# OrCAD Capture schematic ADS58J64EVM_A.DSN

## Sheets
1 PAGE06 - OUTPUT - XILINX CONN: size B; title: OUTPUT - FMC ONNECTOR; rev: A; note: ADS58J64EVM
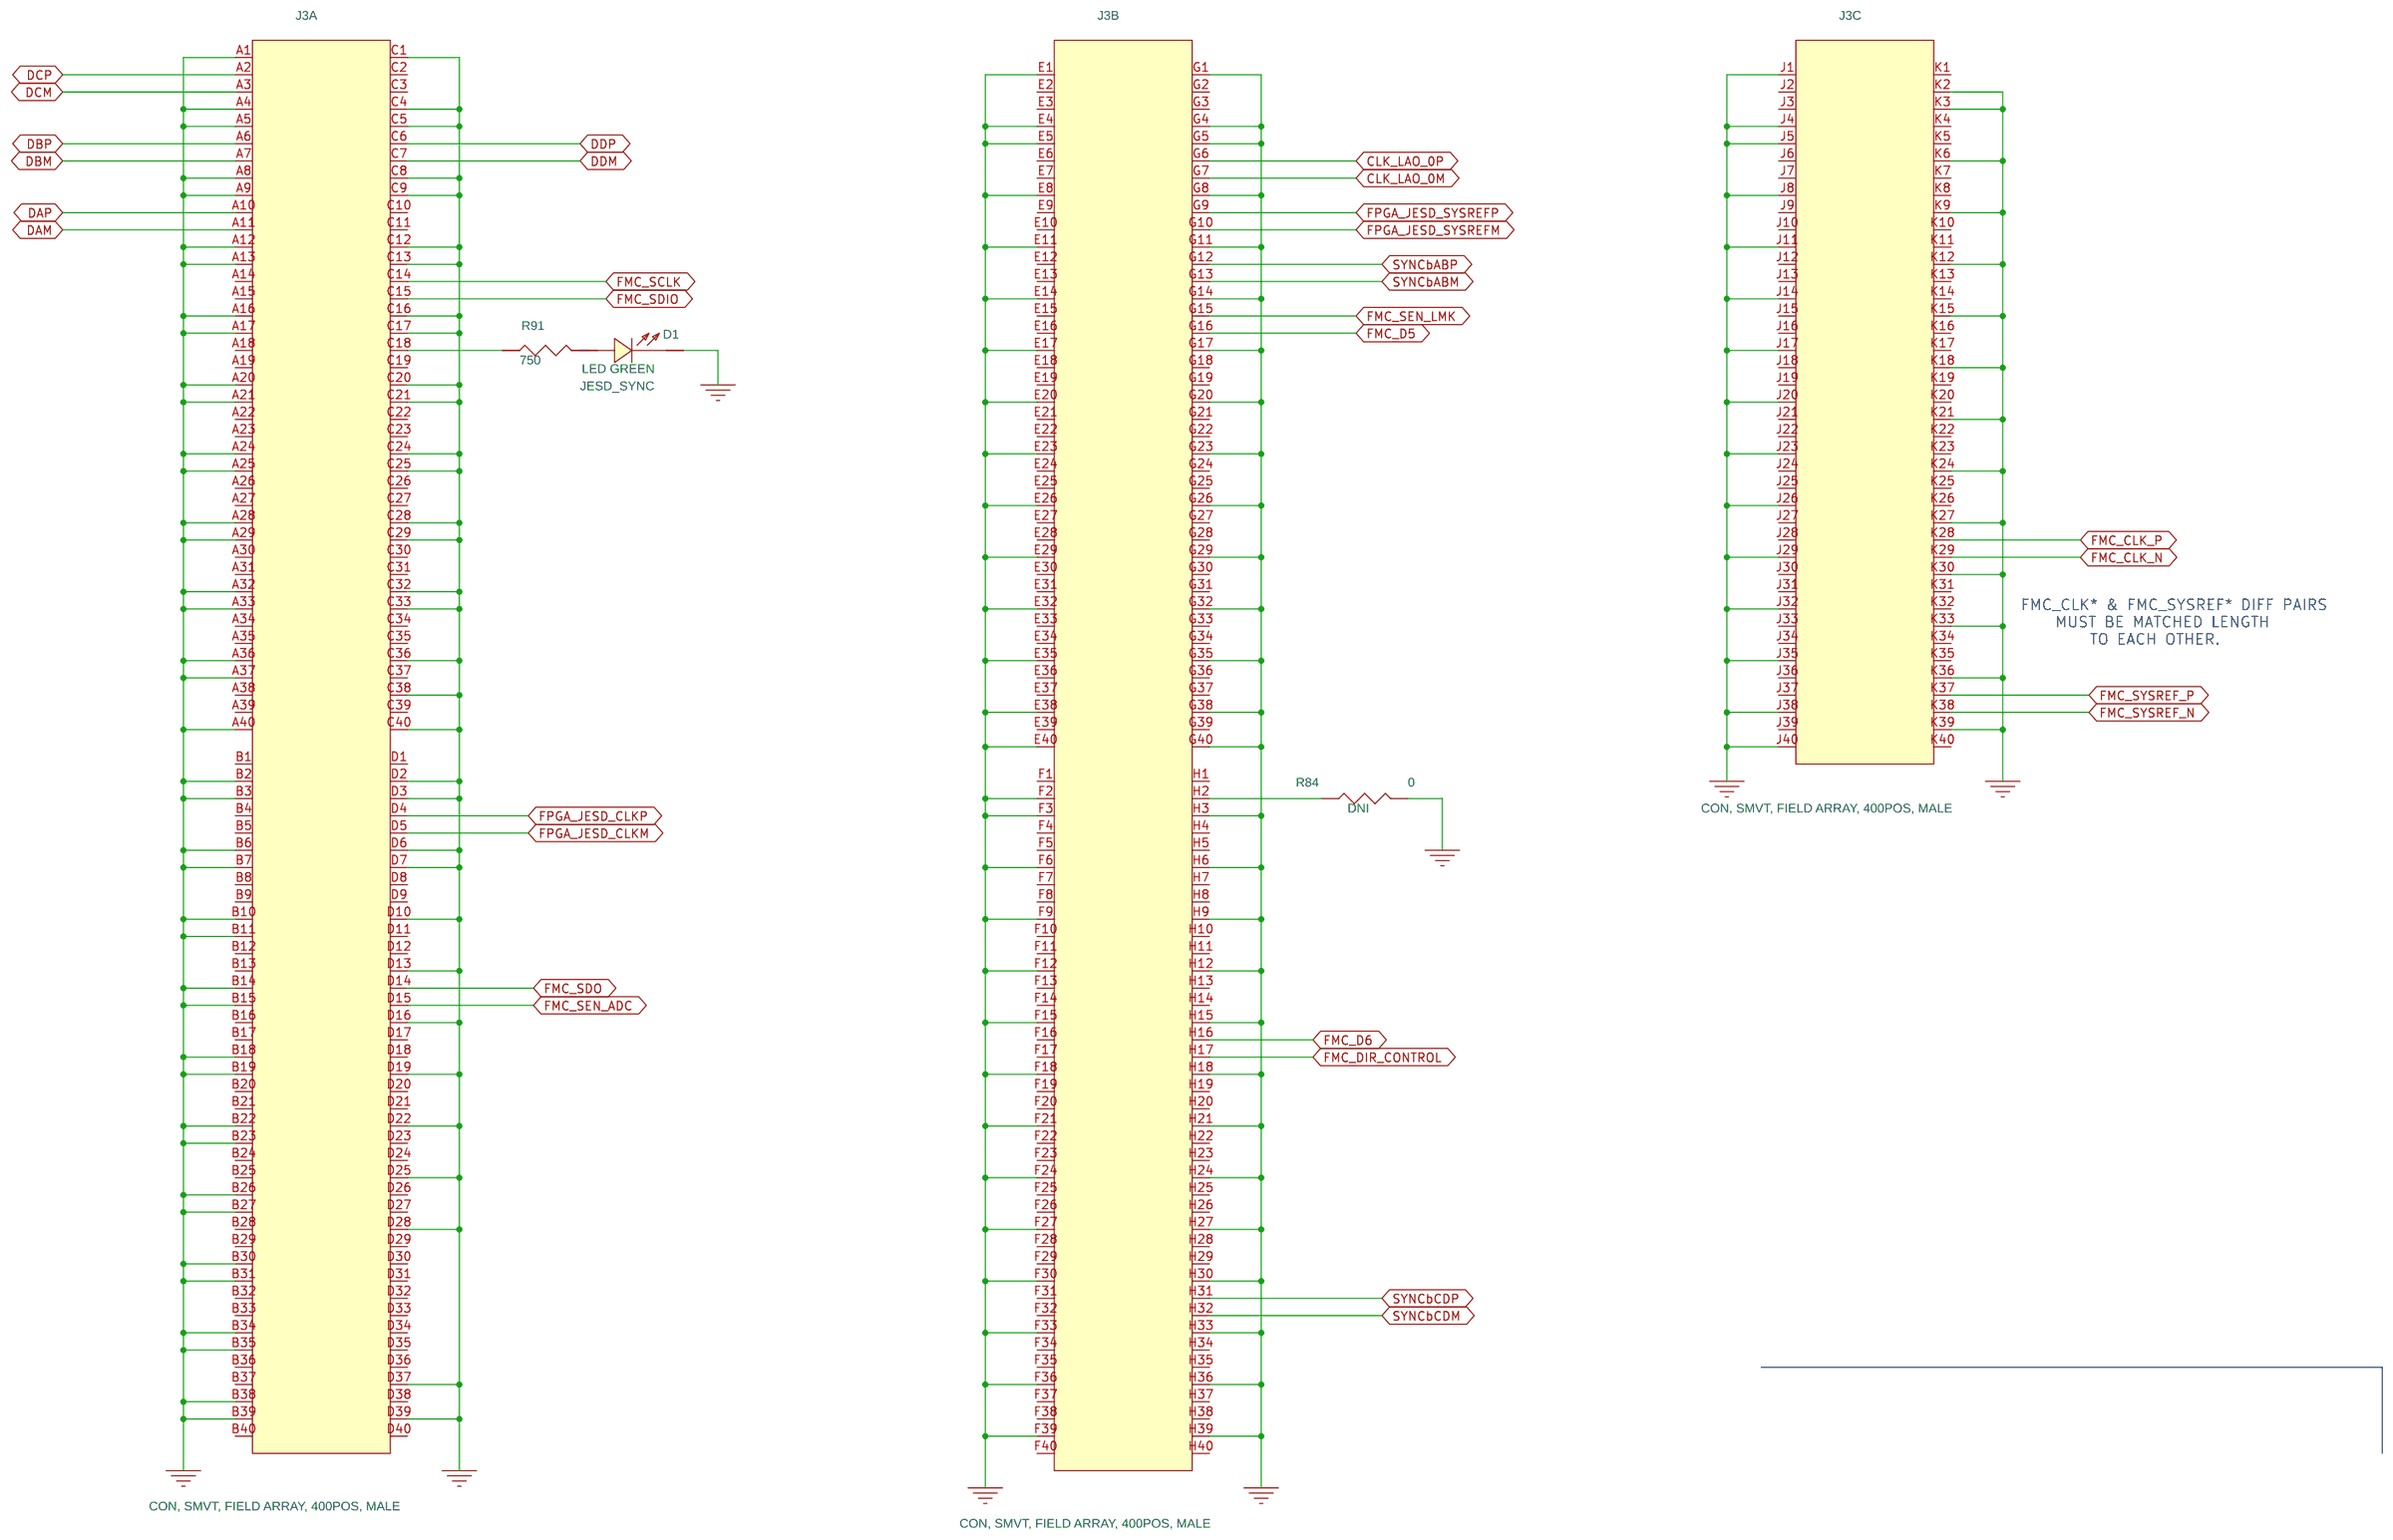
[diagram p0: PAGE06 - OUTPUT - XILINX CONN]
2 PAGE08-  CPLD: size B; title: CPLD
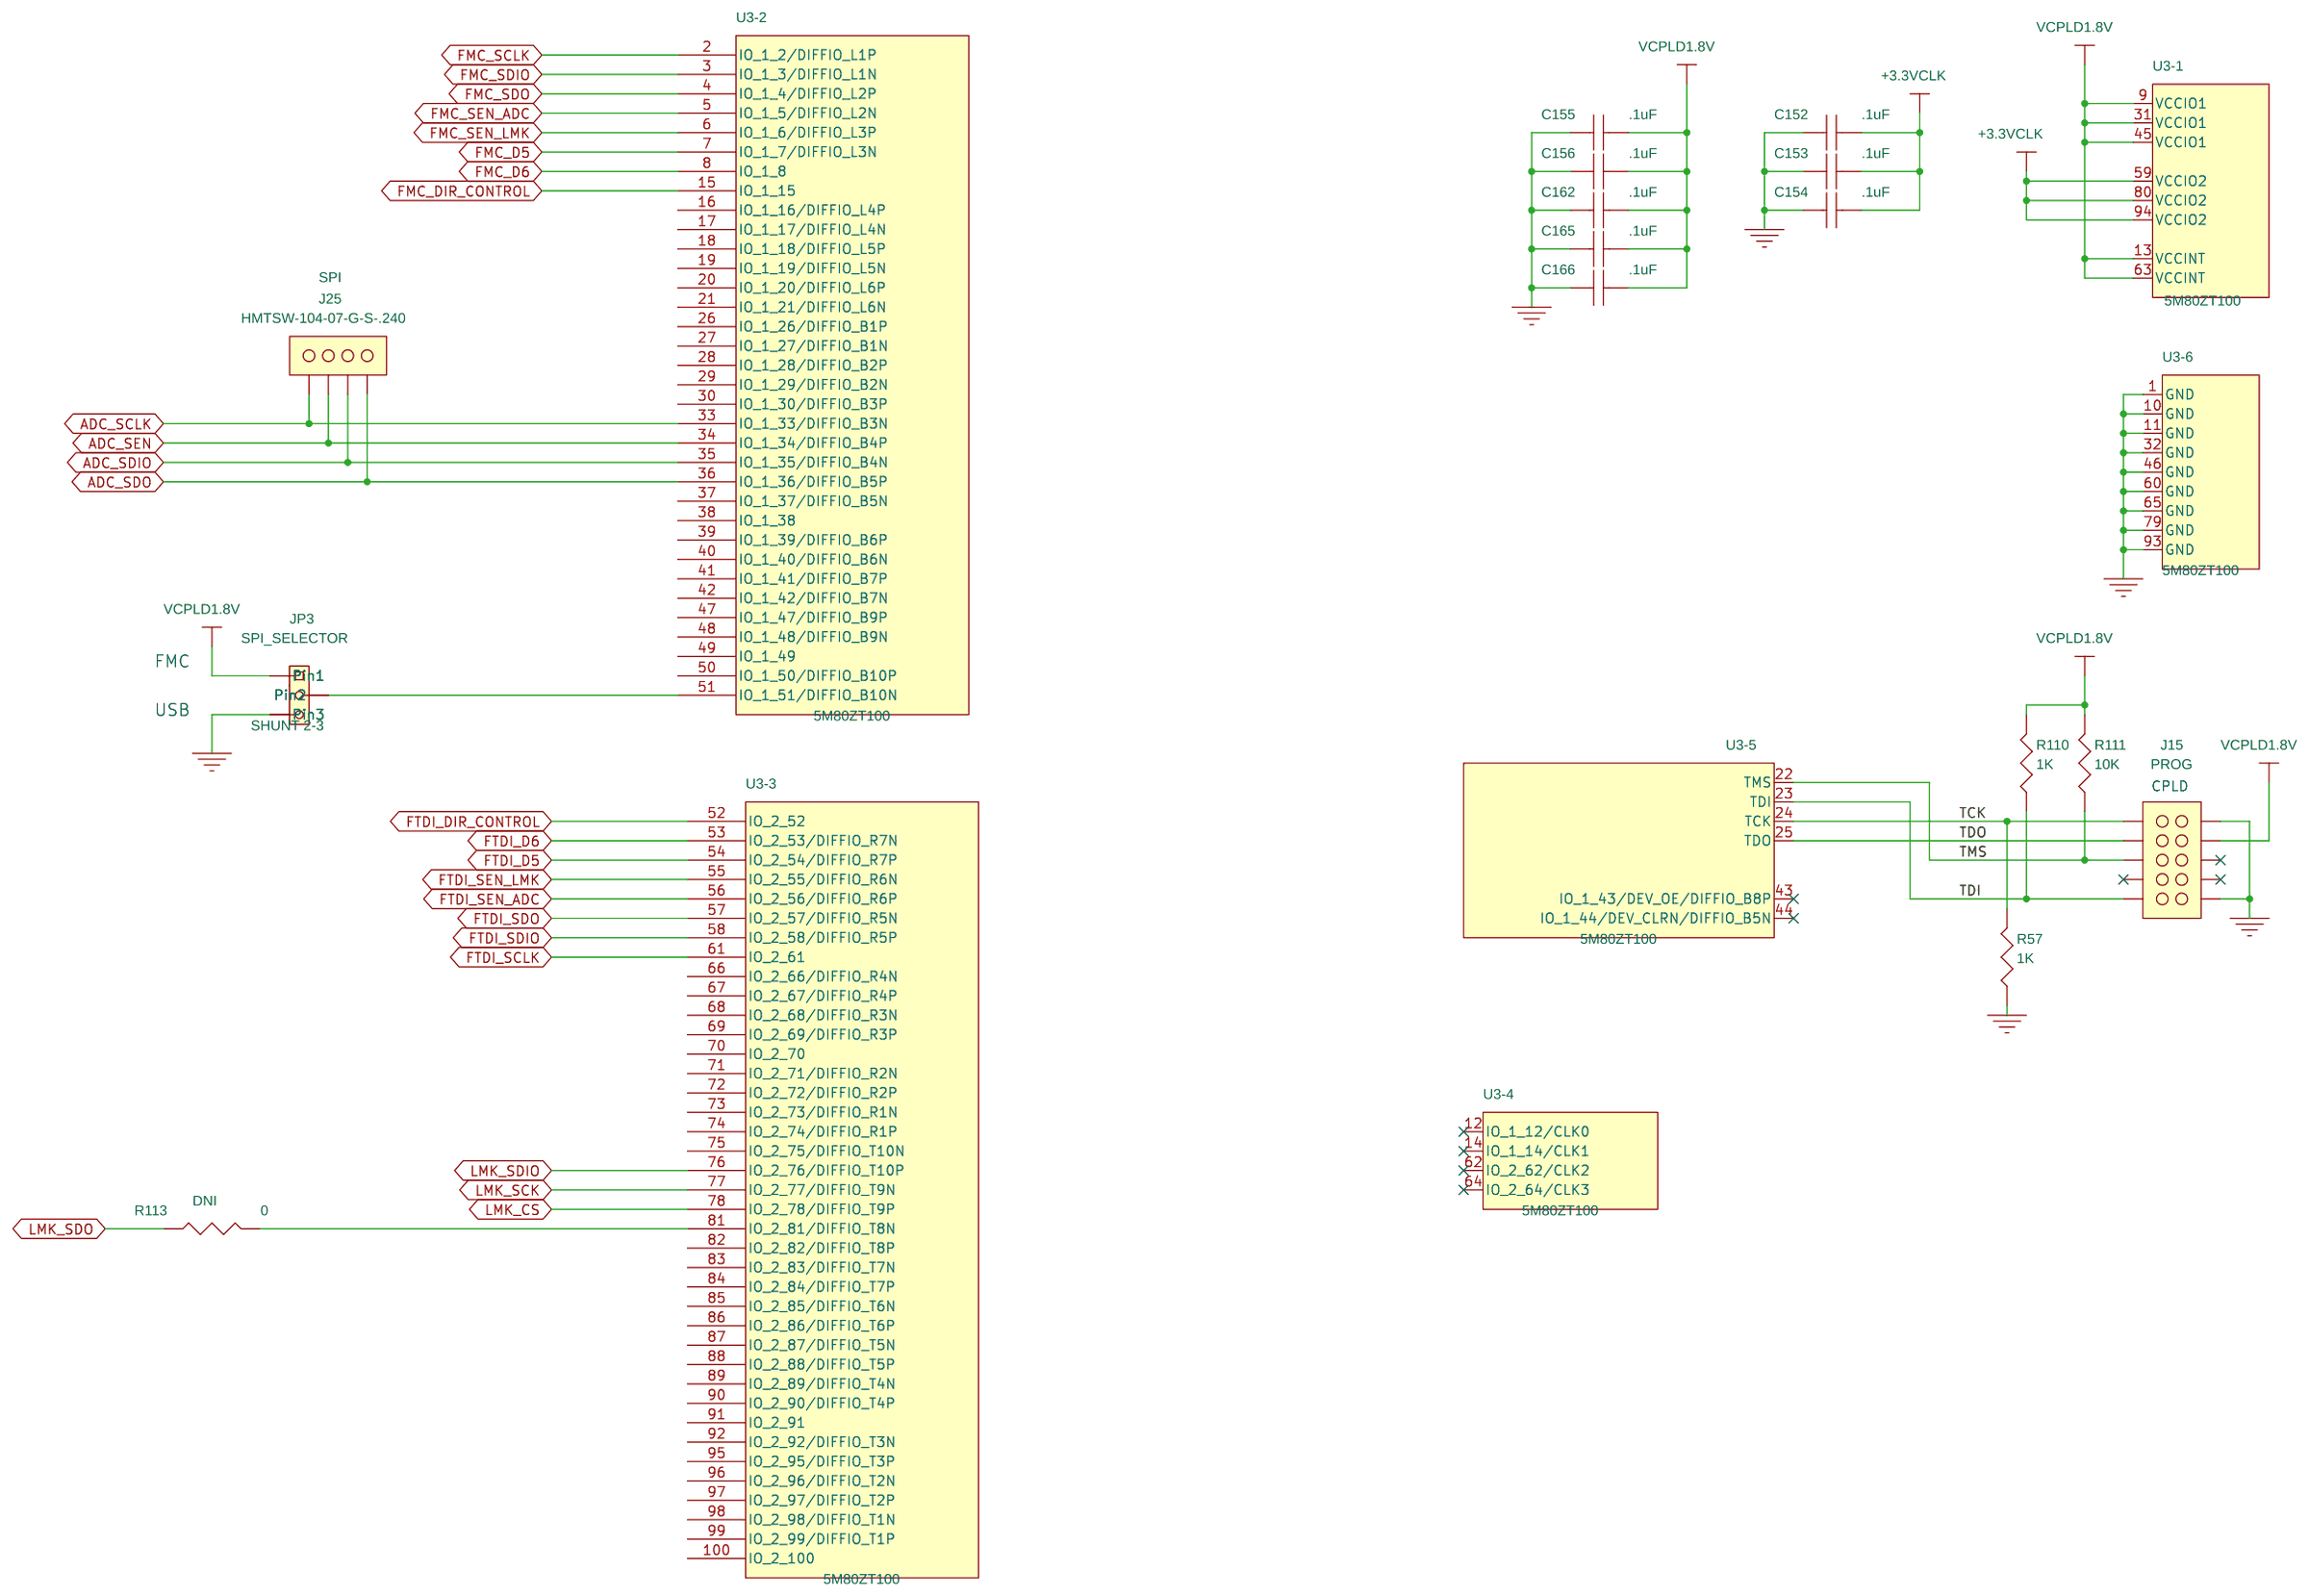
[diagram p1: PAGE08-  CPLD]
3 PAGE04 - LMK: size B; title: CLOCK
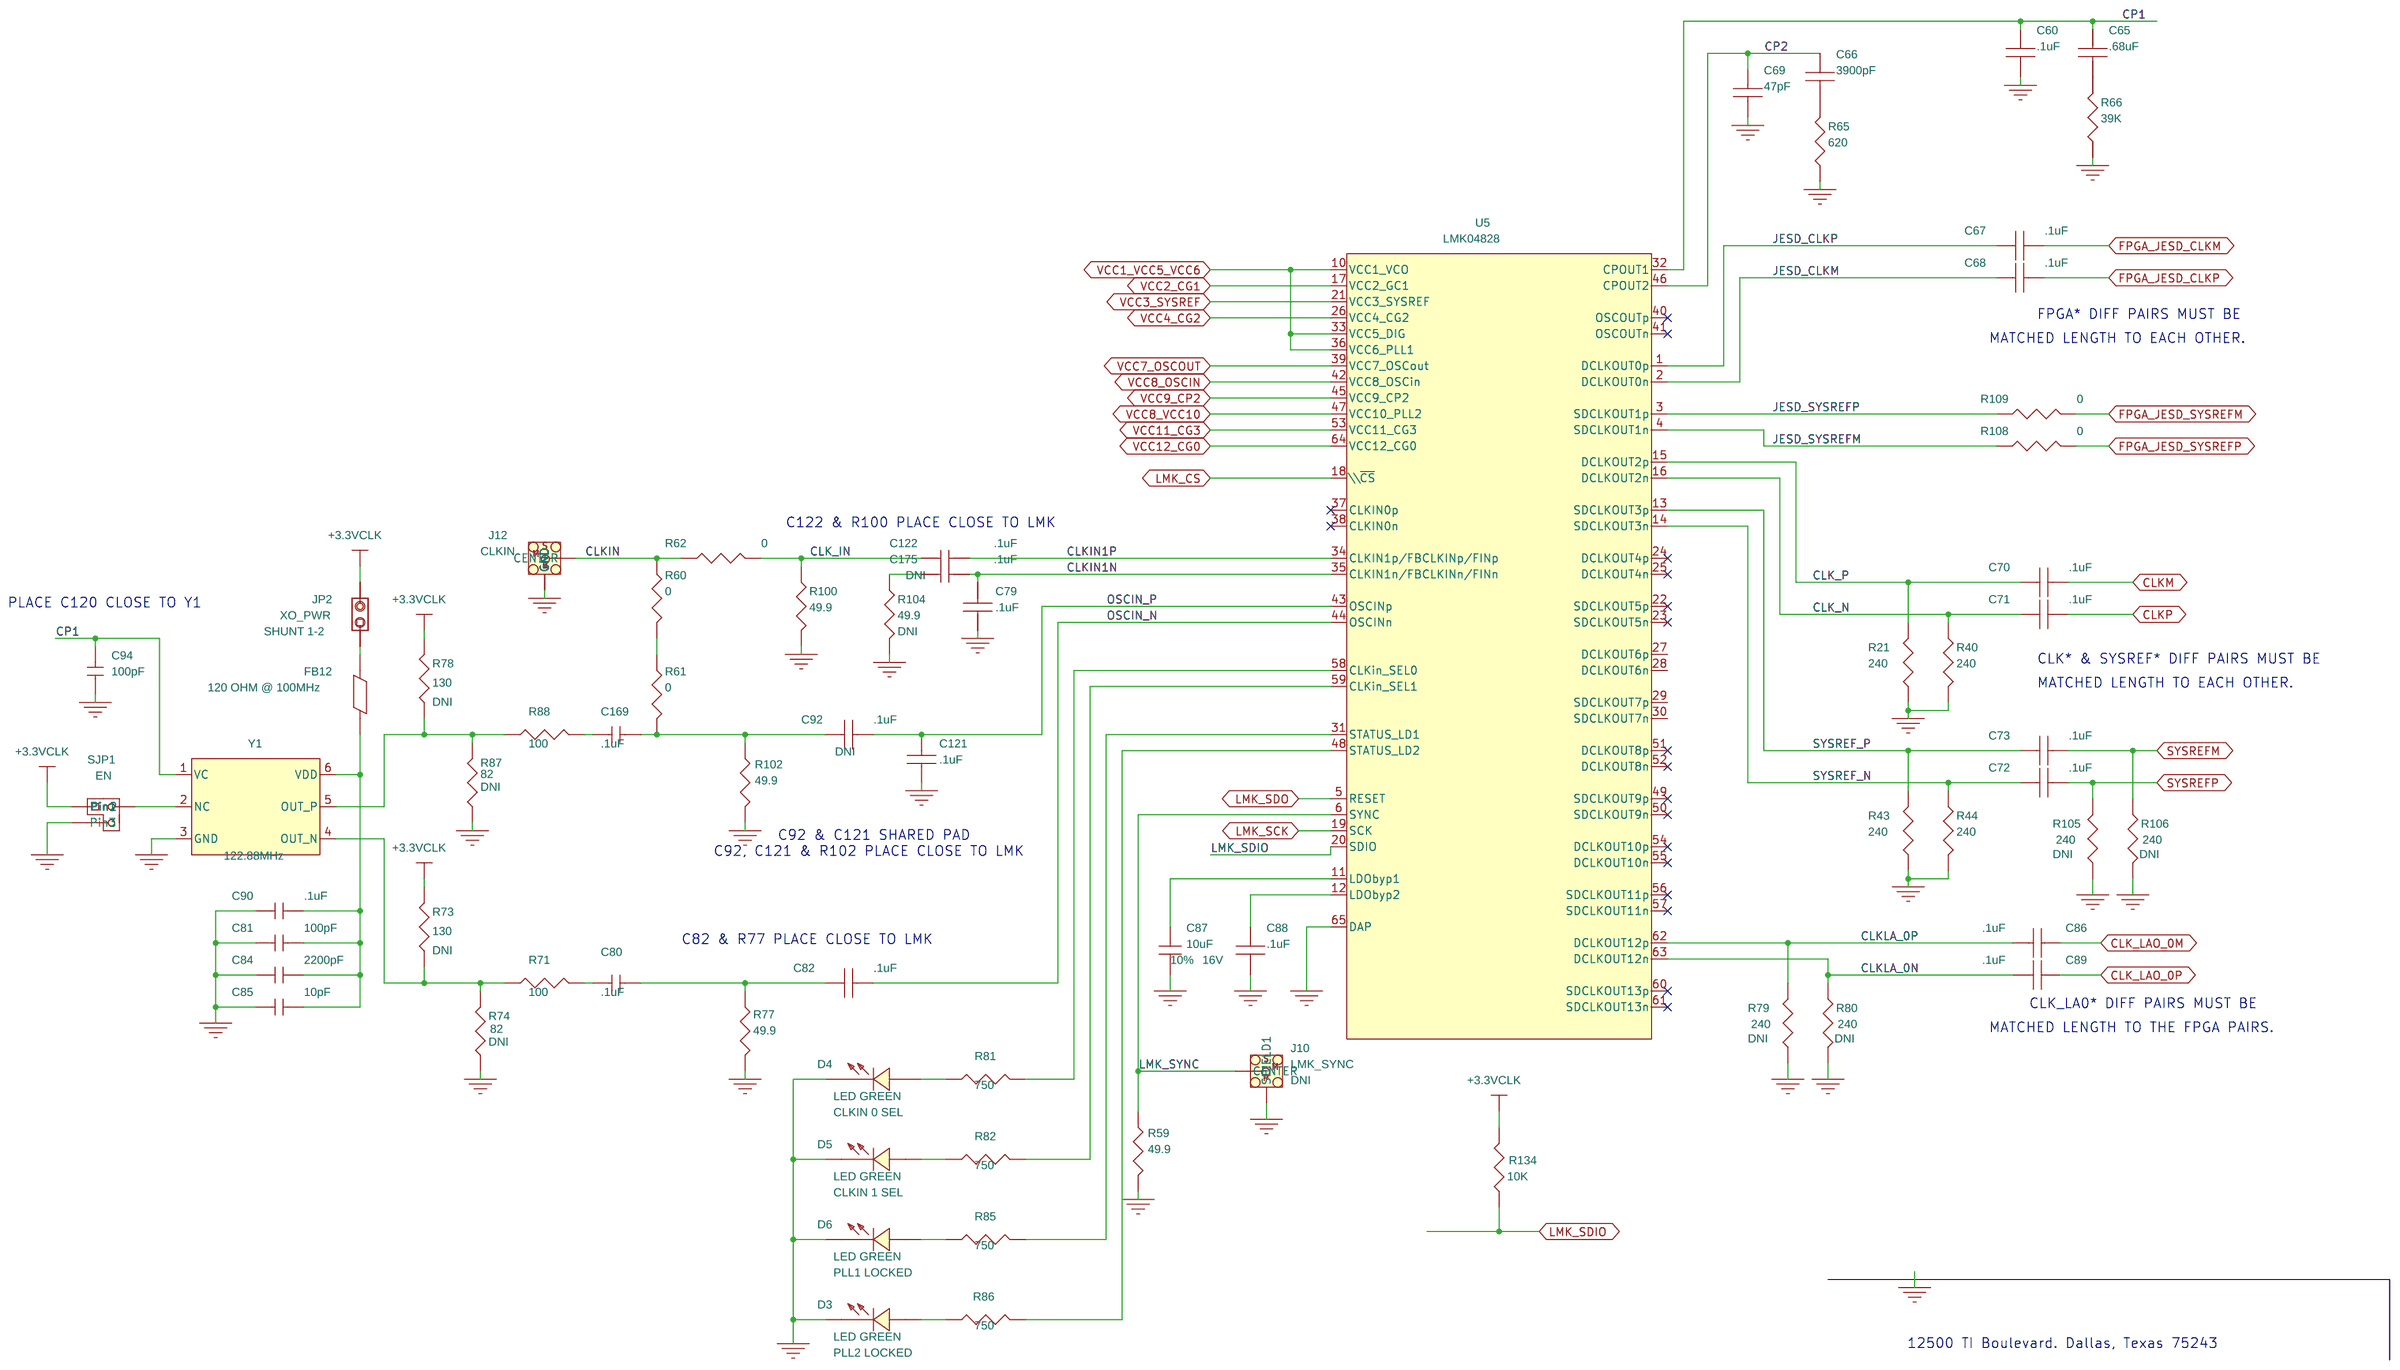
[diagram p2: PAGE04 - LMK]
4 PAGE01 - BLOCK DIAGRAM: title: BLOCK DIAGRAM
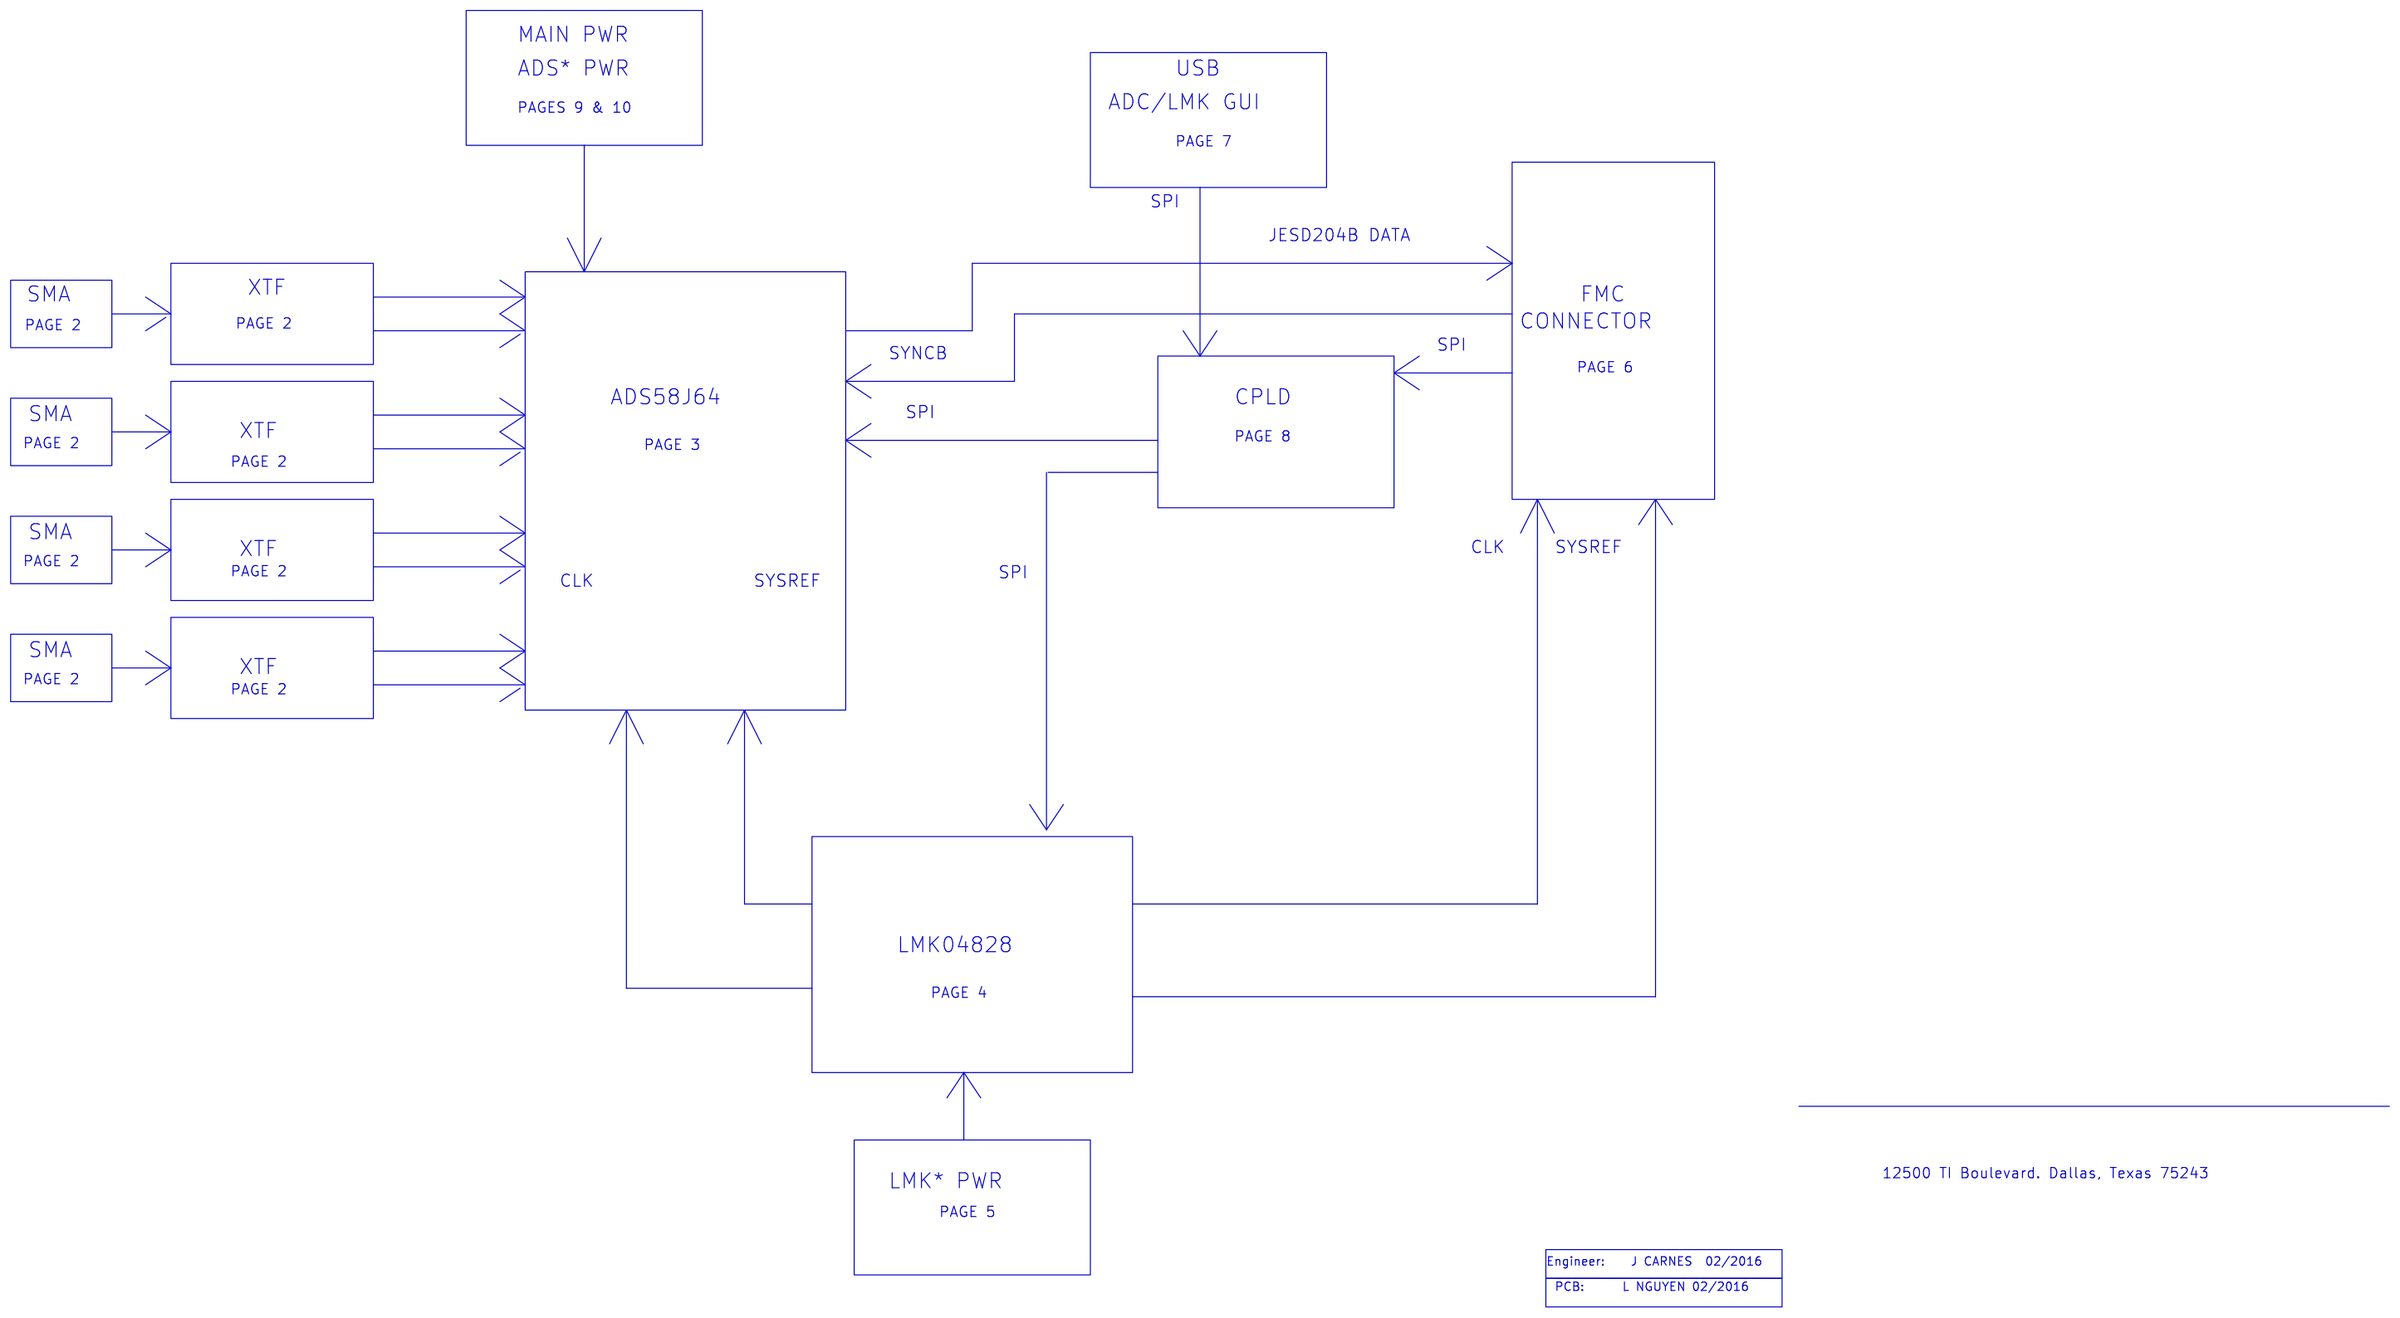
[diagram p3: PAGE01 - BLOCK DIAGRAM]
5 PAGE02 - ANALOG IN: size B; title: ANALOG IN
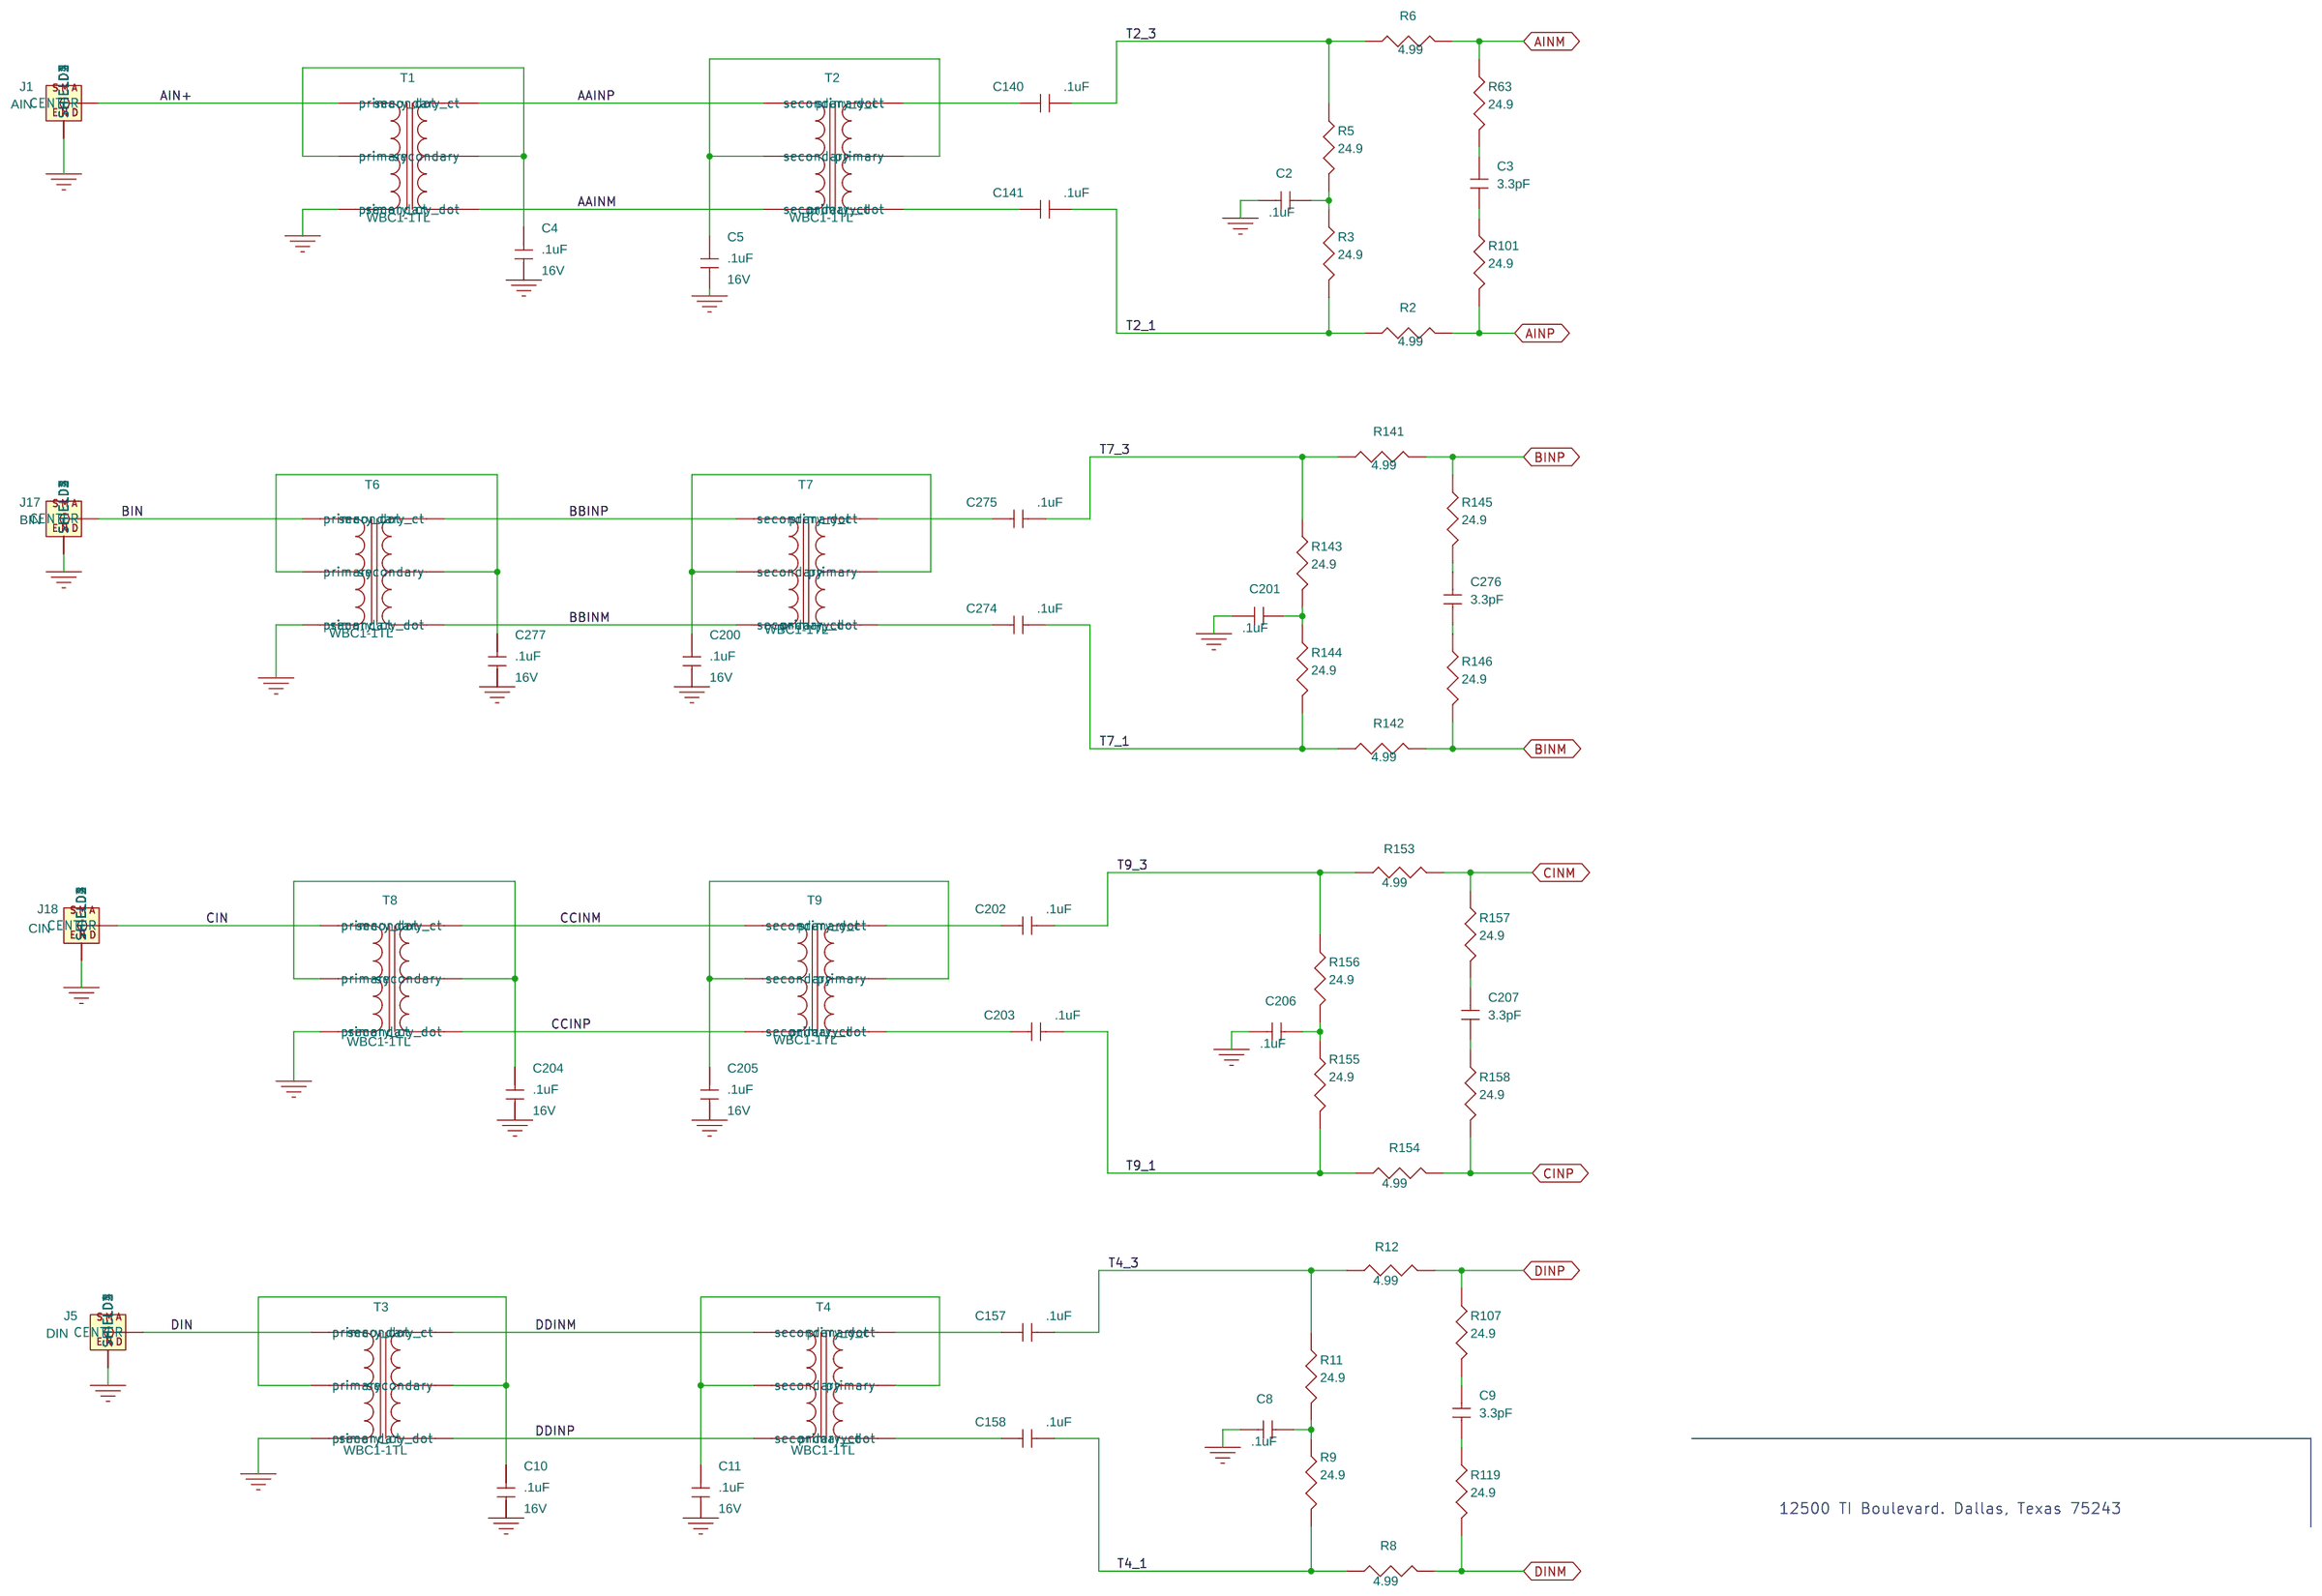
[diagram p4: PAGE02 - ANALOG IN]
6 PAGE03 - ADS58J66_DODSIS: size B; title: ADC
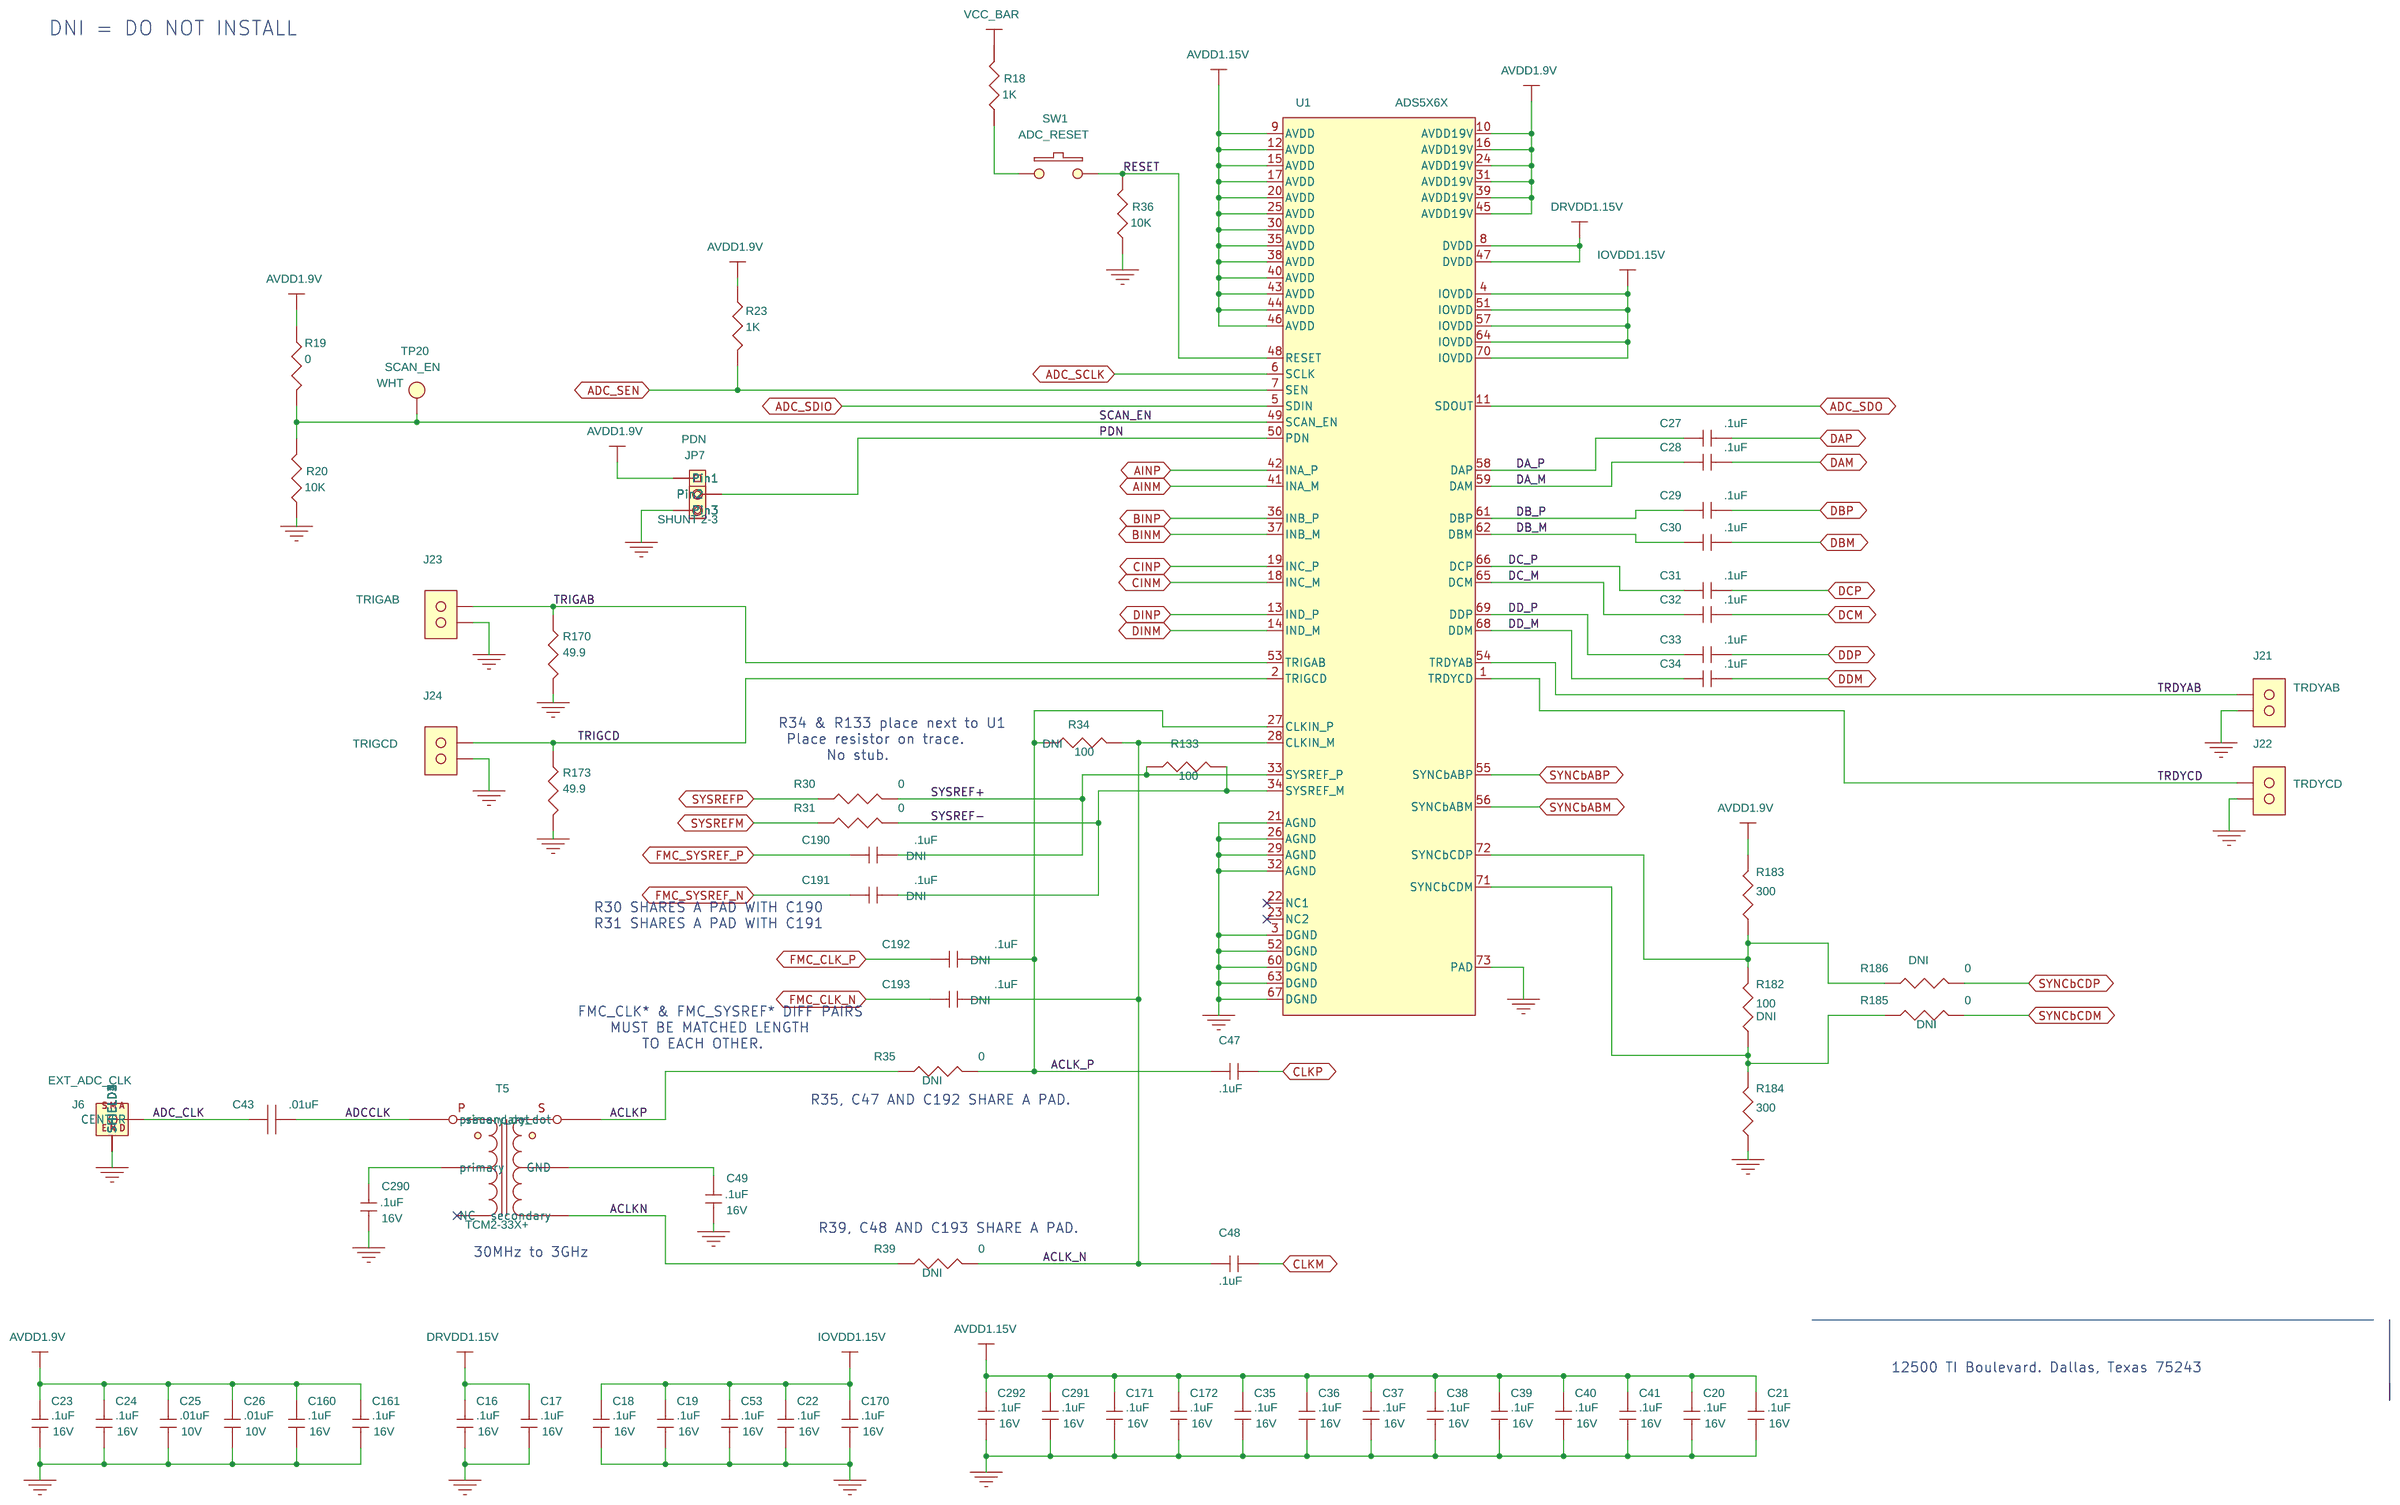
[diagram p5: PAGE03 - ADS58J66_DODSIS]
7 PAGE05 - LMK POWER: size B; title: LMK POWER
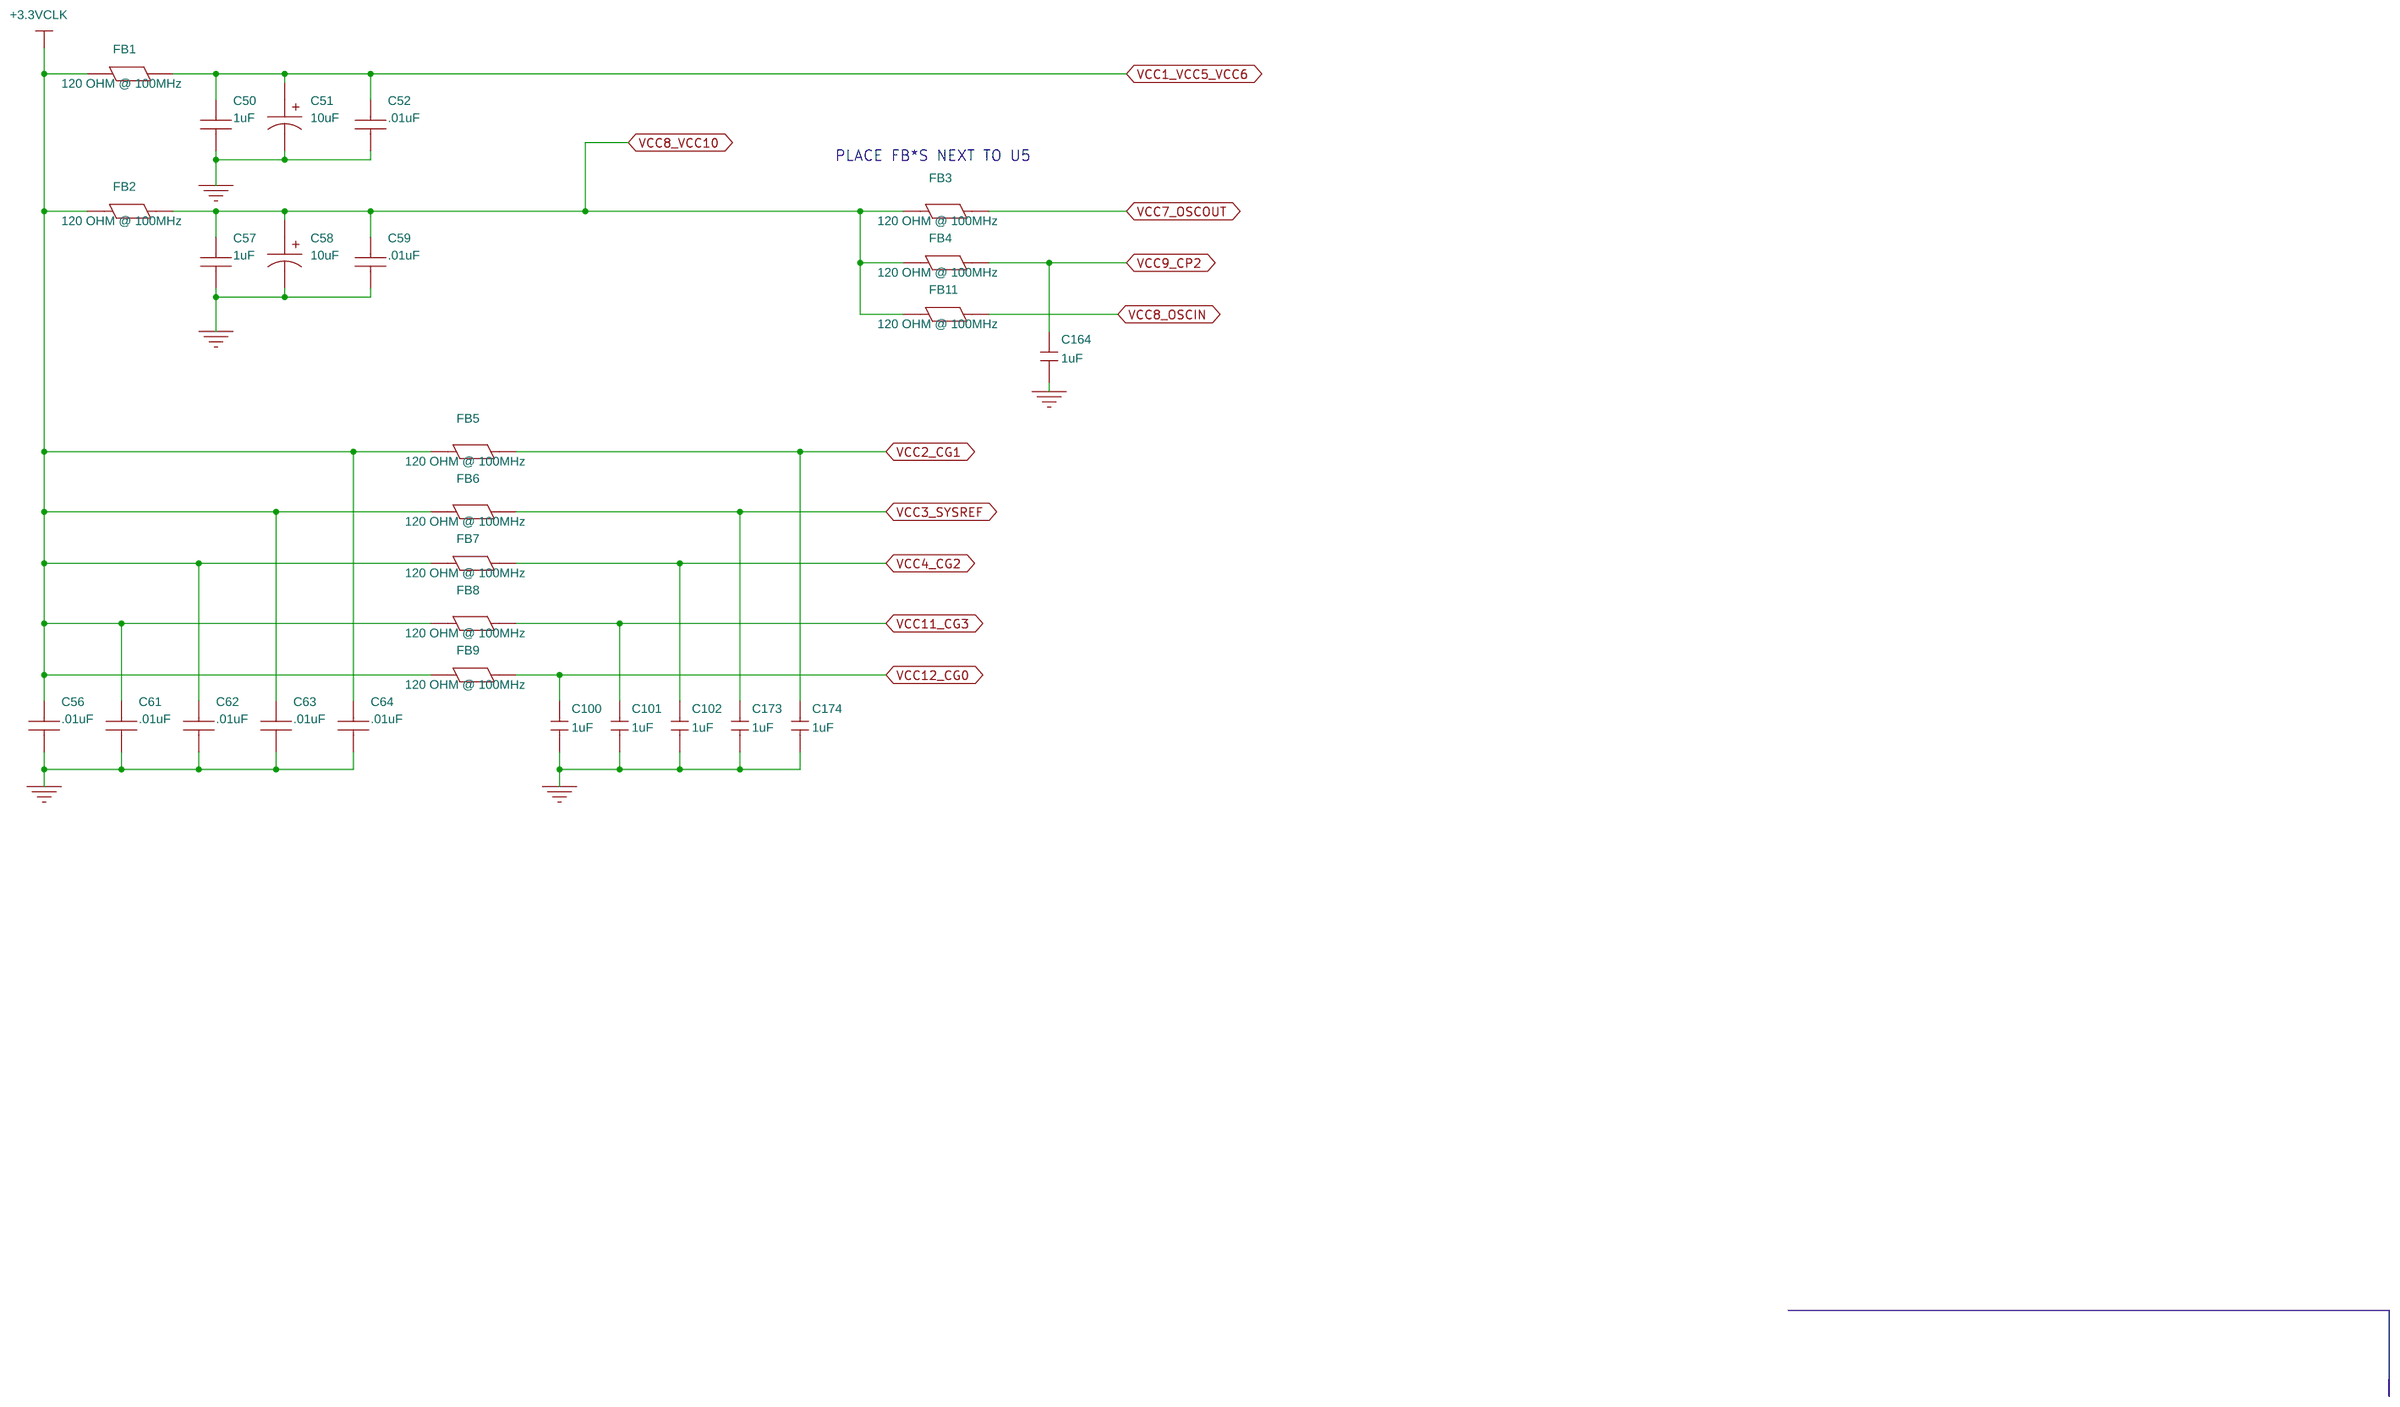
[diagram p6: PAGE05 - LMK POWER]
8 PAGE07 - USB INTERFACE: size B; title: USB
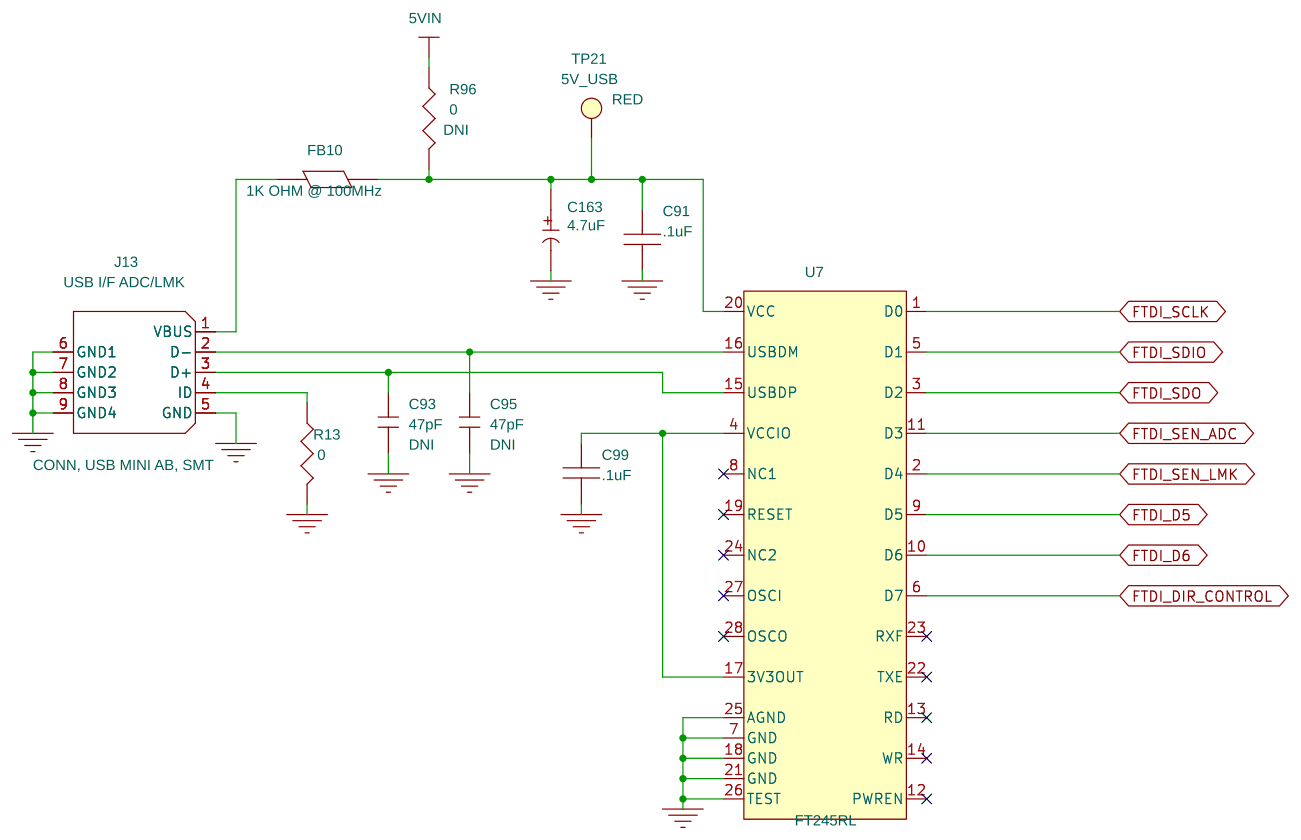
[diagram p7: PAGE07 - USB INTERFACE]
9 PAGE09 - MAIN POWER SUPPLIES: size B; title: MAIN POWER
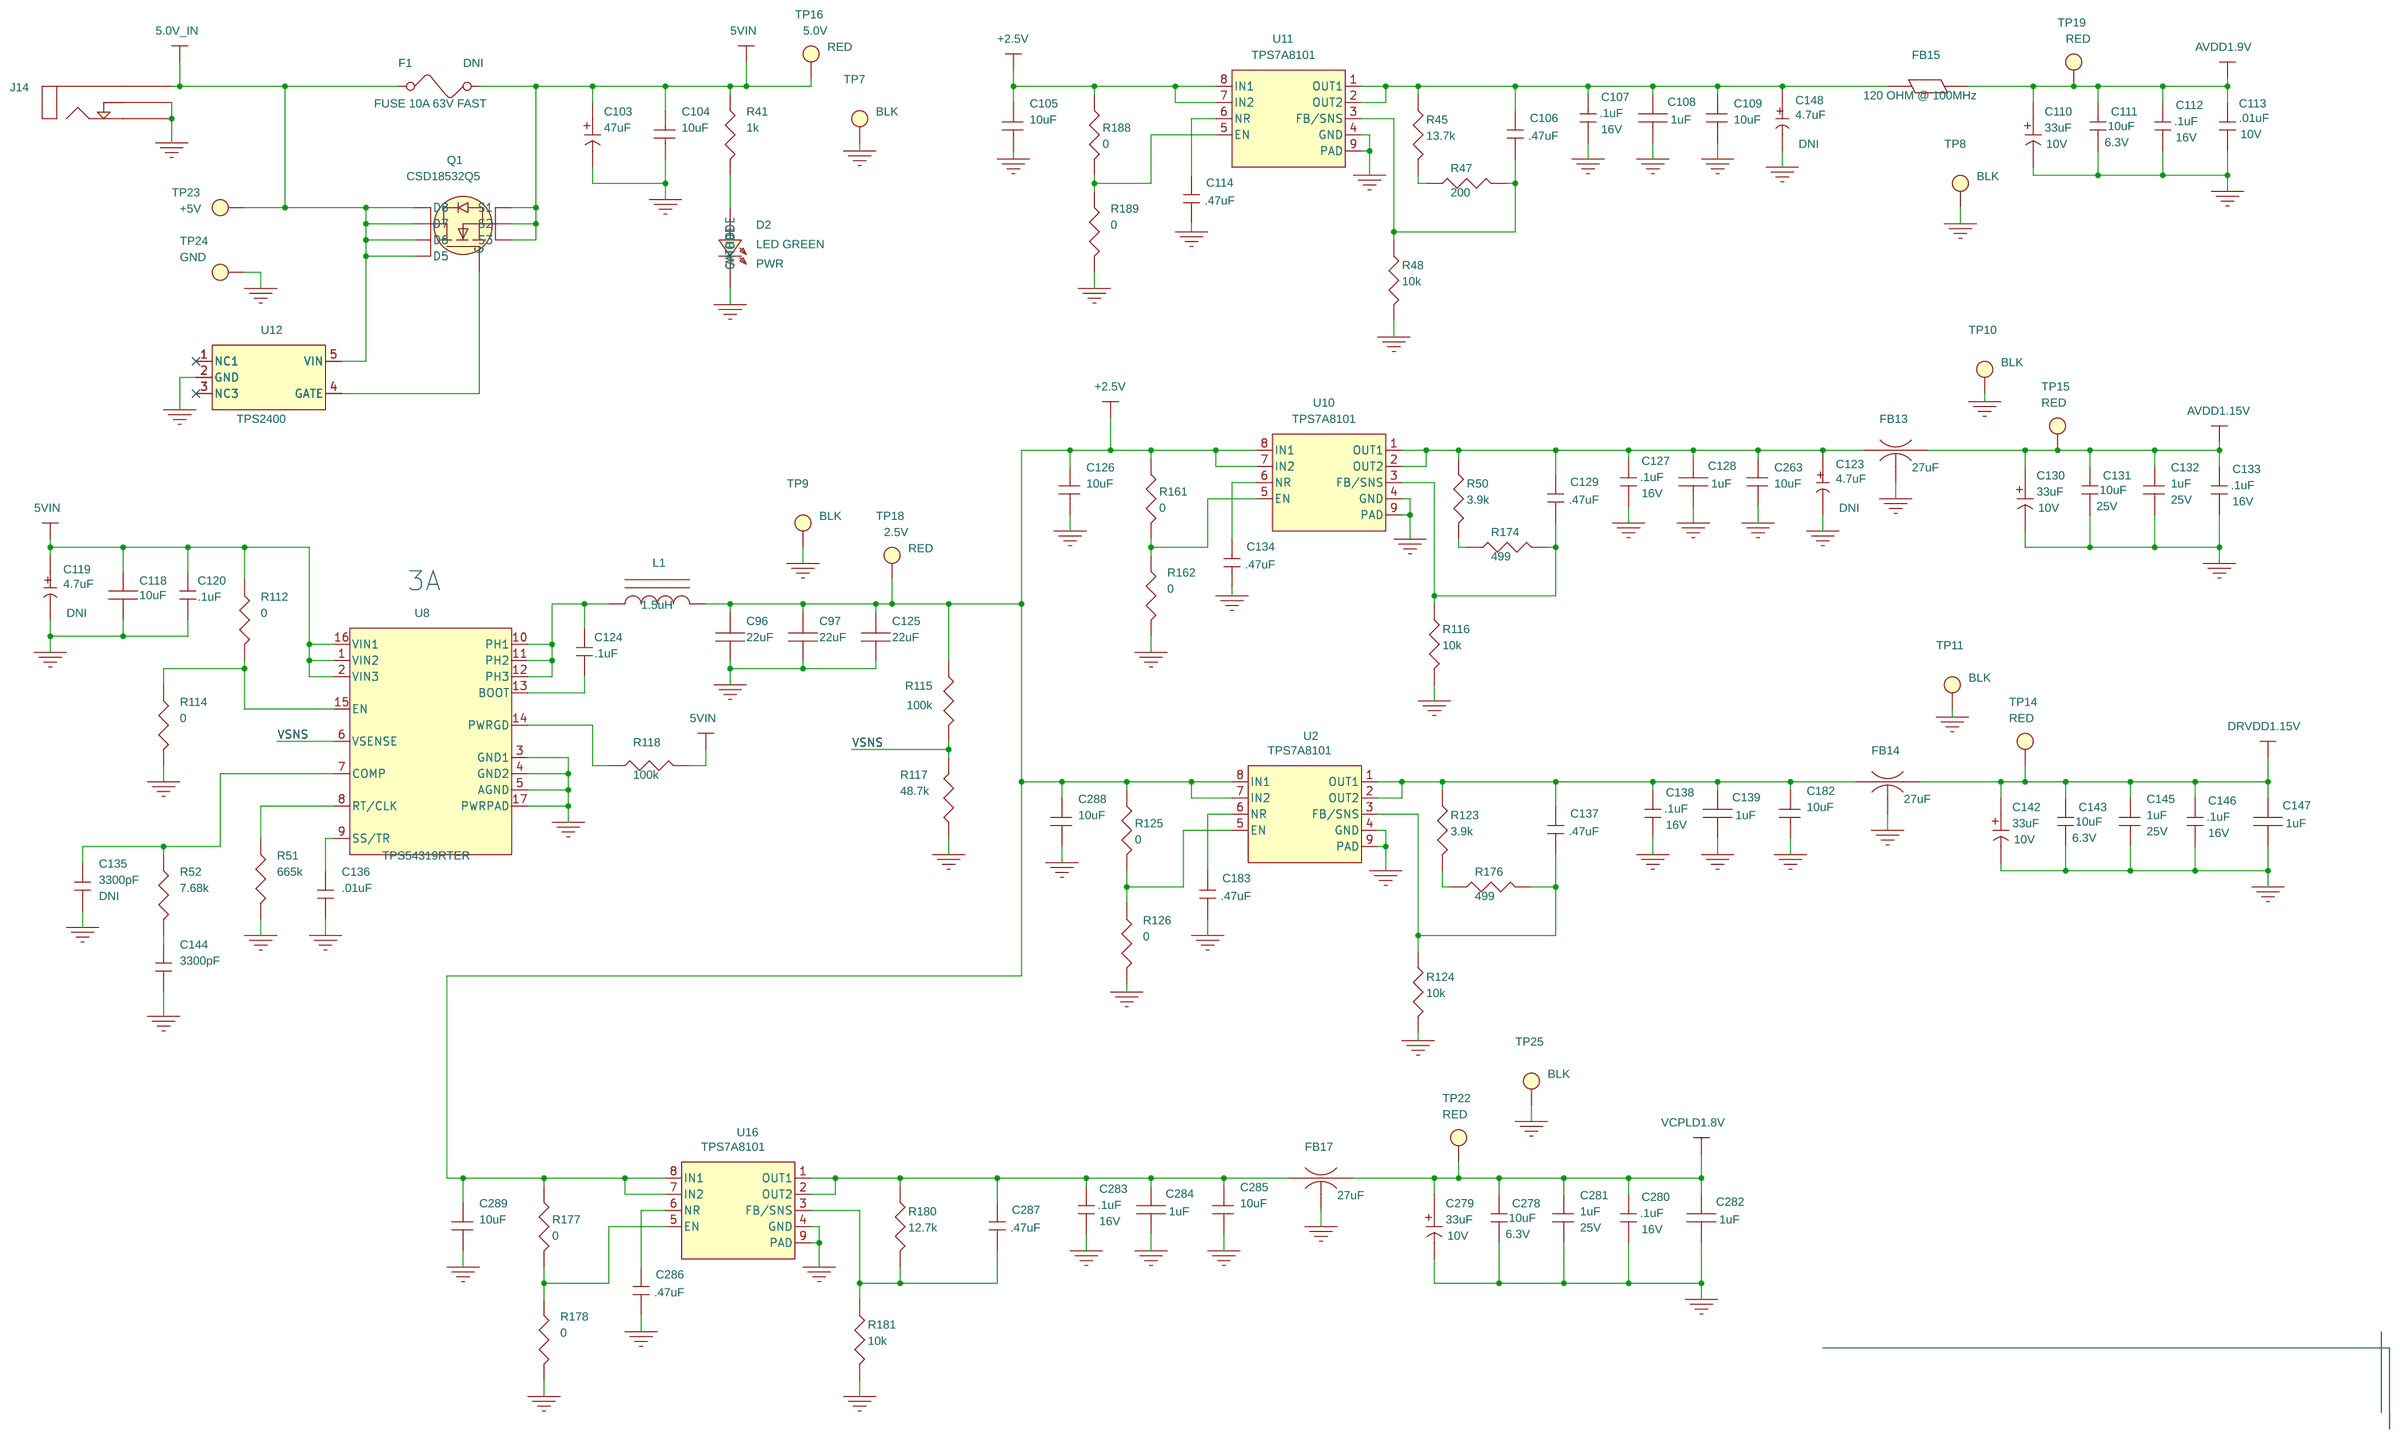
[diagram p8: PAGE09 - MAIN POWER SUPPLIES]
10 PAGE10 - PWR 3.3V: size B; title: POWER 3.3V
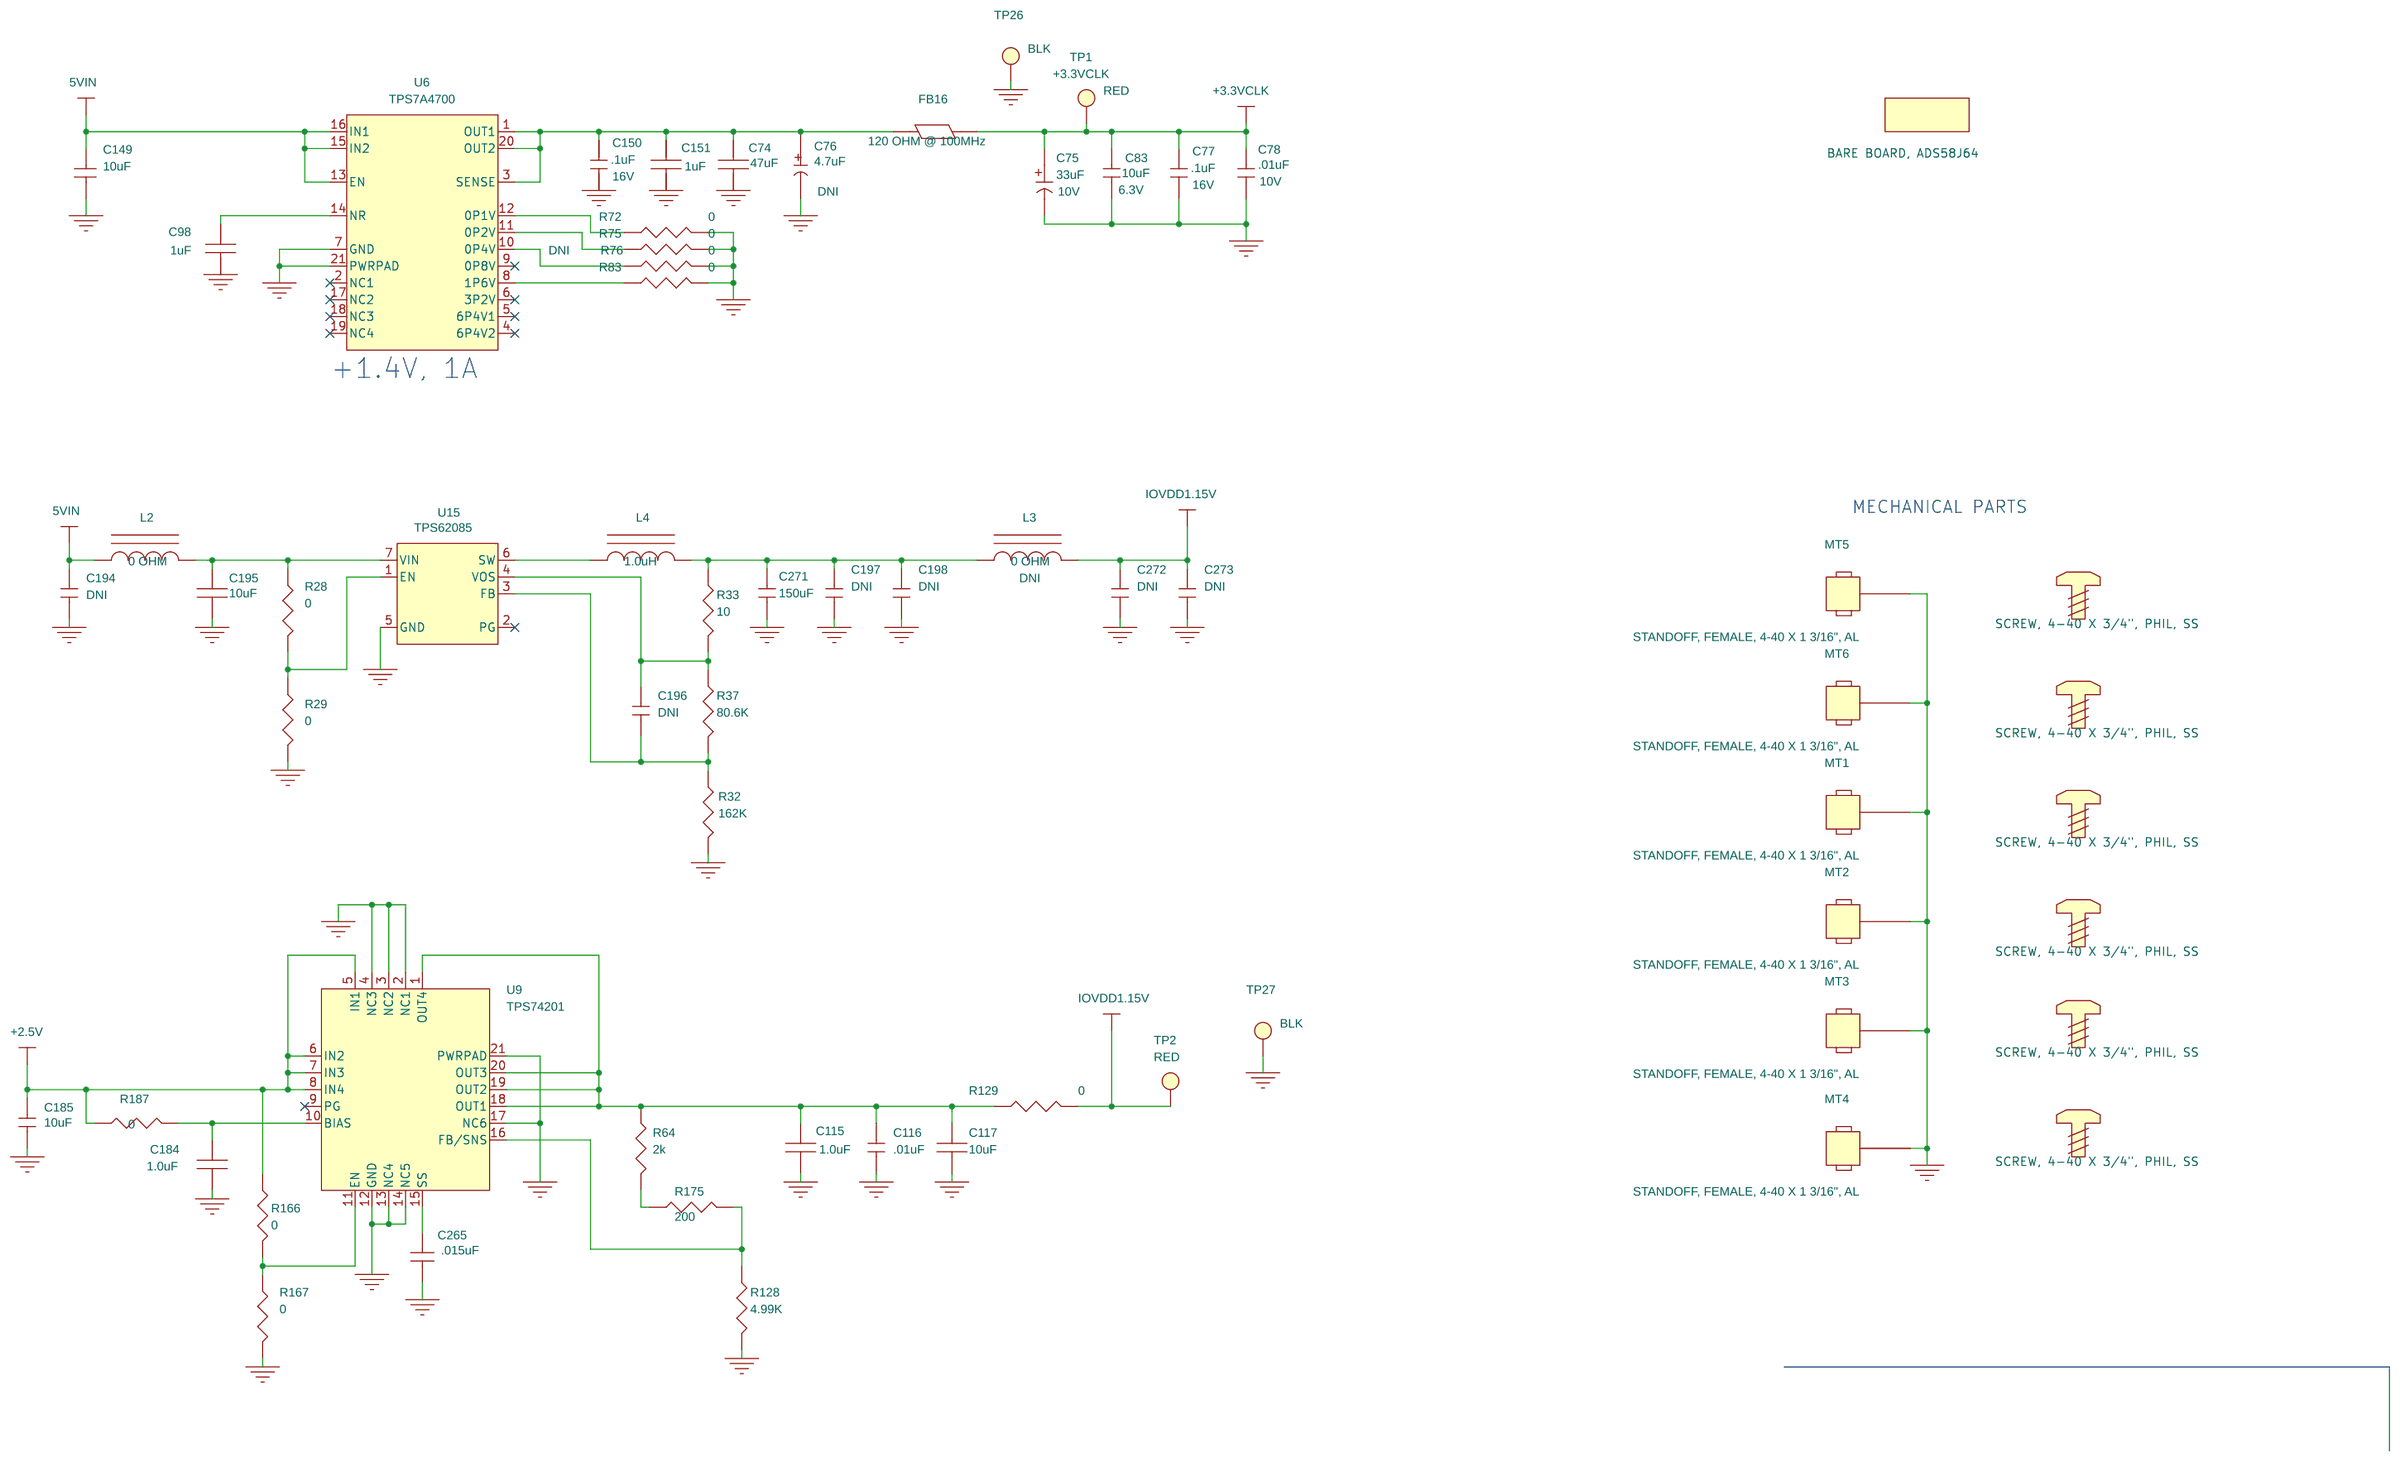
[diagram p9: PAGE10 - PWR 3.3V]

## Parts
sheet PAGE02 - ANALOG IN
C2  .1uF  [0402]
C3  3.3pF  [0402]
C4  .1uF  [0402]
C5  .1uF  [0402]
C8  .1uF  [0402]
C9  3.3pF  [0402]
C10  .1uF  [0402]
C11  .1uF  [0402]
C140  .1uF  [0402]
C141  .1uF  [0402]
C157  .1uF  [0402]
C158  .1uF  [0402]
C200  .1uF  [0402]
C201  .1uF  [0402]
C202  .1uF  [0402]
C203  .1uF  [0402]
C204  .1uF  [0402]
C205  .1uF  [0402]
C206  .1uF  [0402]
C207  3.3pF  [0402]
C274  .1uF  [0402]
C275  .1uF  [0402]
C276  3.3pF  [0402]
C277  .1uF  [0402]
J1  CONN, SMA, JACK, 50 OHM, EDGE MNT  [SMA_SMEL_DUAL_PSF-S01_250x215]
J5  CONN, SMA, JACK, 50 OHM, EDGE MNT  [SMA_SMEL_DUAL_PSF-S01_250x215]
J17  CONN, SMA, JACK, 50 OHM, EDGE MNT  [SMA_SMEL_DUAL_PSF-S01_250x215]
J18  CONN, SMA, JACK, 50 OHM, EDGE MNT  [SMA_SMEL_DUAL_PSF-S01_250x215]
R2  4.99  [0402]
R3  24.9  [0402]
R5  24.9  [0402]
R6  4.99  [0402]
R8  4.99  [0402]
R9  24.9  [0402]
R11  24.9  [0402]
R12  4.99  [0402]
R63  24.9  [0402]
R101  24.9  [0402]
R107  24.9  [0402]
R119  24.9  [0402]
R141  4.99  [0402]
R142  4.99  [0402]
R143  24.9  [0402]
R144  24.9  [0402]
R145  24.9  [0402]
R146  24.9  [0402]
R153  4.99  [0402]
R154  4.99  [0402]
R155  24.9  [0402]
R156  24.9  [0402]
R157  24.9  [0402]
R158  24.9  [0402]
T1  WBC1-1TL  [TFMR_6_150X150_60]
T2  WBC1-1TL  [TFMR_6_150X150_60]
T3  WBC1-1TL  [TFMR_6_150X150_60]
T4  WBC1-1TL  [TFMR_6_150X150_60]
T6  WBC1-1TL  [TFMR_6_150X150_60]
T7  WBC1-1TL  [TFMR_6_150X150_60]
T8  WBC1-1TL  [TFMR_6_150X150_60]
T9  WBC1-1TL  [TFMR_6_150X150_60]
sheet PAGE03 - ADS58J66_DODSIS
C16  .1uF  [0201]
C17  .1uF  [0201]
C18  .1uF  [0201]
C19  .1uF  [0201]
C20  .1uF  [0201]
C21  .1uF  [0201]
C22  .1uF  [0201]
C23  .1uF  [0201]
C24  .1uF  [0201]
C25  .01uF  [0201]
C26  .01uF  [0201]
C27  .1uF  [0201]
C28  .1uF  [0201]
C29  .1uF  [0201]
C30  .1uF  [0201]
C31  .1uF  [0201]
C32  .1uF  [0201]
C33  .1uF  [0201]
C34  .1uF  [0201]
C35  .1uF  [0201]
C36  .1uF  [0201]
C37  .1uF  [0201]
C38  .1uF  [0201]
C39  .1uF  [0201]
C40  .1uF  [0201]
C41  .1uF  [0201]
C43  .01uF  [0603]
C47  .1uF  [0201]
C48  .1uF  [0201]
C49  .1uF  [0402]
C53  .1uF  [0201]
C160  .1uF  [0201]
C161  .1uF  [0201]
C170  .1uF  [0201]
C171  .1uF  [0201]
C172  .1uF  [0201]
C190  .1uF  [0201]
C191  .1uF  [0201]
C192  .1uF  [0201]
C193  .1uF  [0201]
C290  .1uF  [0402]
C291  .1uF  [0201]
C292  .1uF  [0201]
J6  CONN, SMA, JACK, 50 OHM, EDGE MNT  [SMA_SMEL_DUAL_PSF-S01_250x215]
J21  HMTSW-102-07-G-S-.240  [HDR_THVT_1x2_100_M]
J22  HMTSW-102-07-G-S-.240  [HDR_THVT_1x2_100_M]
J23  HMTSW-102-07-G-S-.240  [HDR_THVT_1x2_100_M]
J24  HMTSW-102-07-G-S-.240  [HDR_THVT_1x2_100_M]
JP7  HDR, THVT, 3POS  [HDR_THVT_1X3_100_M]
R18  1K  [0402]
R19  0  [0402]
R20  10K  [0402]
R23  1K  [0402]
R30  0  [0201]
R31  0  [0201]
R34  100  [0201]
R35  0  [0201]
R36  10K  [0402]
R39  0  [0201]
R133  100  [0201]
R170  49.9  [0402]
R173  49.9  [0402]
R182  100  [0201]
R183  300  [0201]
R184  300  [0201]
R185  0  [0201]
R186  0  [0201]
SW1  SWITCH, SMT, PUSHBUTTON  [SW_SMVT_SPST_EVQPJX_2]
T5  TCM2-33X+  [TFMR_6_160x150_50]
TP20  WHT  [TESTPOINT_62DRILL_THM]
U1  ADS5X6X  [QFN_72_10MMX10MM_0P50MM_PWRPAD]
Z_SH-J38  SHUNT-HEADER
sheet PAGE04 - LMK
C60  .1uF  [0402]
C65  .68uF  [0402]
C66  3900pF  [0402]
C67  .1uF  [0402]
C68  .1uF  [0402]
C69  47pF  [0402]
C70  .1uF  [0402]
C71  .1uF  [0402]
C72  .1uF  [0402]
C73  .1uF  [0402]
C79  .1uF  [0402]
C80  .1uF  [0402]
C81  100pF  [0603]
C82  .1uF  [0402]
C84  2200pF  [0402]
C85  10pF  [0402]
C86  .1uF  [0402]
C87  10uF  [0603]
C88  .1uF  [0402]
C89  .1uF  [0402]
C90  .1uF  [0402]
C92  .1uF  [0402]
C94  100pF  [0603]
C121  .1uF  [0402]
C122  .1uF  [0402]
C169  .1uF  [0402]
C175  .1uF  [0402]
D3  LED GREEN  [LED_1206]
D4  LED GREEN  [LED_1206]
D5  LED GREEN  [LED_1206]
D6  LED GREEN  [LED_1206]
FB12  120 OHM @ 100MHz  [1206]
J10  CONN, SMP, PLUG, 50 OHM, THVT  [smp_b120]
J12  CONN, SMA, JACK, 50 OHM, THVT  [SMA_THVT_312x312]
JP2  HDR, THVT, 2POS  [HDR_THVT_1X2_100_M]
R21  240  [0402]
R40  240  [0402]
R43  240  [0402]
R44  240  [0402]
R59  49.9  [0402]
R60  0  [0402]
R61  0  [0402]
R62  0  [0402]
R65  620  [0402]
R66  39K  [0402]
R71  100  [0402]
R73  130  [0603]
R74  82  [0603]
R77  49.9  [0402]
R78  130  [0603]
R79  240  [0402]
R80  240  [0402]
R81  750  [0603]
R82  750  [0603]
R85  750  [0603]
R86  750  [0603]
R87  82  [0603]
R88  100  [0402]
R100  49.9  [0402]
R102  49.9  [0402]
R104  49.9  [0402]
R105  240  [0402]
R106  240  [0402]
R108  0  [0402]
R109  0  [0402]
R134  10K  [0402]
SJP1  JUMPER_L_0603_SMT  [JUMPER_SMD_L_0603]
U5  LMK04828  [QFN_64_360X360_0P50MM_PWRPAD]
Y1  122.88MHz  [VCXO_6_CUSTOM]
Z_SH-J7  SHUNT-HEADER
sheet PAGE05 - LMK POWER
C50  1uF  [0402]
C51  10uF  [3528]
C52  .01uF  [0402]
C56  .01uF  [0402]
C57  1uF  [0402]
C58  10uF  [3528]
C59  .01uF  [0402]
C61  .01uF  [0402]
C62  .01uF  [0402]
C63  .01uF  [0402]
C64  .01uF  [0402]
C100  1uF  [0402]
C101  1uF  [0402]
C102  1uF  [0402]
C164  1uF  [0402]
C173  1uF  [0402]
C174  1uF  [0402]
FB1  120 OHM @ 100MHz  [1206]
FB2  120 OHM @ 100MHz  [1206]
FB3  120 OHM @ 100MHz  [1206]
FB4  120 OHM @ 100MHz  [1206]
FB5  120 OHM @ 100MHz  [1206]
FB6  120 OHM @ 100MHz  [1206]
FB7  120 OHM @ 100MHz  [1206]
FB8  120 OHM @ 100MHz  [1206]
FB9  120 OHM @ 100MHz  [1206]
FB11  120 OHM @ 100MHz  [1206]
sheet PAGE06 - OUTPUT - XILINX CONN
D1  LED GREEN  [LED_1206]
J3  CON, SMVT, FIELD ARRAY, 400POS, MALE  [CON_SMVT_40x10_SEAM_MTG]  (sections A,B,C)
R84  0  [0402]
R91  750  [0603]
sheet PAGE07 - USB INTERFACE
C91  .1uF  [0402]
C93  47pF  [0402]
C95  47pF  [0402]
C99  .1uF  [0402]
C163  4.7uF  [TANT_B]
FB10  1K OHM @ 100MHz  [1806]
J13  CONN, USB MINI AB, SMT  [CON_SMRT_USBMNE20_F]
R13  0  [0603]
R96  0  [0603]
TP21  RED  [TESTPOINT_62DRILL_THM]
U7  FT245RL  [ssop_28_413x220_26]
sheet PAGE08-  CPLD
C152  .1uF  [0402]
C153  .1uF  [0402]
C154  .1uF  [0402]
C155  .1uF  [0402]
C156  .1uF  [0402]
C162  .1uF  [0402]
C165  .1uF  [0402]
C166  .1uF  [0402]
J15  HDR, THVT, HI-TEMP, 5POS  [HDR_THVT_2x5_100_M]
J25  HMTSW-104-07-G-S-.240  [HDR_THVT_1x4_100_M]
JP3  HDR, THVT, 3POS  [HDR_THVT_1X3_100_M]
R57  1K  [0402]
R110  1K  [0402]
R111  10K  [0402]
R113  0  [0402]
U3  5M80ZT100  [tqfp_100_551x551_20]  (sections -1,-2,-3,-4,-5,-6)
Z_SH-H4  SHUNT-HEADER
sheet PAGE09 - MAIN POWER SUPPLIES
C96  22uF  [1210]
C97  22uF  [1210]
C103  47uF  [TANT_B]
C104  10uF  [0805]
C105  10uF  [0805]
C106  .47uF  [0603]
C107  .1uF  [0402]
C108  1uF  [0603]
C109  10uF  [0805]
C110  33uF  [TANT_B]
C111  10uF  [0805]
C112  .1uF  [0402]
C113  .01uF  [0201]
C114  .47uF  [0603]
C118  10uF  [1206]
C119  4.7uF  [TANT_B]
C120  .1uF  [0603]
C123  4.7uF  [TANT_B]
C124  .1uF  [0603]
C125  22uF  [1210]
C126  10uF  [0805]
C127  .1uF  [0402]
C128  1uF  [0603]
C129  .47uF  [0603]
C130  33uF  [TANT_B]
C131  10uF  [0805]
C132  1uF  [0603]
C133  .1uF  [0402]
C134  .47uF  [0603]
C135  3300pF  [0603]
C136  .01uF  [0603]
C137  .47uF  [0603]
C138  .1uF  [0402]
C139  1uF  [0603]
C142  33uF  [TANT_B]
C143  10uF  [0805]
C144  3300pF  [0603]
C145  1uF  [0603]
C146  .1uF  [0402]
C147  1uF  [0603]
C148  4.7uF  [TANT_B]
C182  10uF  [0805]
C183  .47uF  [0603]
C263  10uF  [0805]
C278  10uF  [0805]
C279  33uF  [TANT_B]
C280  .1uF  [0402]
C281  1uF  [0603]
C282  1uF  [0603]
C283  .1uF  [0402]
C284  1uF  [0603]
C285  10uF  [0805]
C286  .47uF  [0603]
C287  .47uF  [0603]
C288  10uF  [0805]
C289  10uF  [0805]
D2  LED GREEN  [LED_1206]
F1  FUSE 10A 63V FAST  [1206]
FB13  27uF  [1206_BEAD_NFM31P]
FB14  27uF  [1206_BEAD_NFM31P]
FB15  120 OHM @ 100MHz  [1206]
FB17  27uF  [1206_BEAD_NFM31P]
J14  CONN, JACK, PWR, MINI, R/A, TH  [CON_RAPC722_JACK_THVT_3]
L1  1.5uH  [IND_SM_MSS1048]
Q1  CSD18532Q5  [SON_Q5B_8]
R41  1k  [0402]
R45  13.7k  [0402]
R47  200  [0402]
R48  10k  [0402]
R50  3.9k  [0402]
R51  665k  [0603]
R52  7.68k  [0603]
R112  0  [0603]
R114  0  [0603]
R115  100k  [0603]
R116  10k  [0402]
R117  48.7k  [0603]
R118  100k  [0603]
R123  3.9k  [0402]
R124  10k  [0402]
R125  0  [0603]
R126  0  [0603]
R161  0  [0603]
R162  0  [0603]
R174  499  [0402]
R176  499  [0402]
R177  0  [0603]
R178  0  [0603]
R180  12.7k  [0402]
R181  10k  [0402]
R188  0  [0603]
R189  0  [0603]
TP7  BLK  [TESTPOINT_62DRILL_THM]
TP8  BLK  [TESTPOINT_62DRILL_THM]
TP9  BLK  [TESTPOINT_62DRILL_THM]
TP10  BLK  [TESTPOINT_62DRILL_THM]
TP11  BLK  [TESTPOINT_62DRILL_THM]
TP14  RED  [TESTPOINT_62DRILL_THM]
TP15  RED  [TESTPOINT_62DRILL_THM]
TP16  RED  [TESTPOINT_62DRILL_THM]
TP18  RED  [TESTPOINT_62DRILL_THM]
TP19  RED  [TESTPOINT_62DRILL_THM]
TP22  RED  [TESTPOINT_62DRILL_THM]
TP23  Testloop_Red  [testpoint_62dia]
TP24  Testloop_Black  [testpoint_62dia]
TP25  BLK  [TESTPOINT_62DRILL_THM]
U2  TPS7A8101  [SON_8_3MMX3MM_0P65MM]
U8  TPS54319RTER  [QFN_16_124x124_PWRPAD]
U10  TPS7A8101  [SON_8_3MMX3MM_0P65MM]
U11  TPS7A8101  [SON_8_3MMX3MM_0P65MM]
U12  TPS2400  [DBV5]
U16  TPS7A8101  [SON_8_3MMX3MM_0P65MM]
sheet PAGE10 - PWR 3.3V
C74  47uF  [1206]
C75  33uF  [TANT_B]
C76  4.7uF  [TANT_B]
C77  .1uF  [0402]
C78  .01uF  [0201]
C83  10uF  [0805]
C98  1uF  [0603]
C115  1.0uF  [0603]
C116  .01uF  [0603]
C117  10uF  [0805]
C149  10uF  [0805]
C150  .1uF  [0402]
C151  1uF  [0603]
C184  1.0uF  [0603]
C185  10uF  [0603]
C194  DNI  [0603]
C195  10uF  [1206]
C196  DNI  [0603]
C197  DNI  [0603]
C198  DNI  [0402]
C265  .015uF  [0402]
C271  150uF  [1210]
C272  DNI  [0603]
C273  DNI  [0402]
FB16  120 OHM @ 100MHz  [1206]
L2  0 OHM  [IND_SM_169x169_XFL4020]
L3  0 OHM  [IND_SM_169x169_XFL4020]
L4  1.0uH  [IND_SM_169x169_XFL4020]
MT1  STANDOFF, FEMALE, 4-40 X 1 3/16", AL  [MFG125_PLATED]
MT2  STANDOFF, FEMALE, 4-40 X 1 3/16", AL  [MFG125_PLATED]
MT3  STANDOFF, FEMALE, 4-40 X 1 3/16", AL  [MFG125_PLATED]
MT4  STANDOFF, FEMALE, 4-40 X 1 3/16", AL  [MFG125_PLATED]
MT5  STANDOFF, FEMALE, 4-40 X 1 3/16", AL  [MFG125_PLATED]
MT6  STANDOFF, FEMALE, 4-40 X 1 3/16", AL  [MFG125_PLATED]
R28  0  [0402]
R29  0  [0402]
R32  162K  [0603]
R33  10  [0603]
R37  80.6K  [0603]
R64  2k  [0402]
R72  0  [0402]
R75  0  [0402]
R76  0  [0402]
R83  0  [0402]
R128  4.99K  [0402]
R129  0  [0805]
R166  0  [0603]
R167  0  [0603]
R175  200  [0402]
R187  0  [0603]
TP1  RED  [TESTPOINT_62DRILL_THM]
TP2  RED  [TESTPOINT_62DRILL_THM]
TP26  BLK  [TESTPOINT_62DRILL_THM]
TP27  BLK  [TESTPOINT_62DRILL_THM]
U6  TPS7A4700  [QFN_20_199x199_0p65mm]
U9  TPS74201  [QFN_20_197X197_0P65_RGW]
U15  TPS62085  [QFN_7_2MMx2MM]
Z_BOARD1  BARE BOARD, ADS58J64
Z_SCREW1  SCREW, 4-40 X 3/4", PHIL, SS
Z_SCREW2  SCREW, 4-40 X 3/4", PHIL, SS
Z_SCREW3  SCREW, 4-40 X 3/4", PHIL, SS
Z_SCREW4  SCREW, 4-40 X 3/4", PHIL, SS
Z_SCREW5  SCREW, 4-40 X 3/4", PHIL, SS
Z_SCREW6  SCREW, 4-40 X 3/4", PHIL, SS

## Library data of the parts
C2 C8 C201 C206 = CAP0402_0: Mfr_Name: MURATA; Mfr_Part_Number: GRM155R71C104KA88D; TOL: 10%; Voltage: 16V
C3 C9 C207 C276 = CAP_0402_2pF: Mfr_Name: AVX CORP; Mfr_Part_Number: 04025U3R3BAT2A
C4 C5 C10 C11 C49 C77 C107 C112 C127 C133 C138 C146 C150 C200 C204 C205 C277 C280 C283 C290 = CAP0603: Mfr_Name: MURATA; Mfr_Part_Number: GRM155R71C104KA88D; TOL: 10%; Voltage: 16V
C140 C141 C157 C158 C202 C203 C274 C275 = CAP_0603_0.1uF_H: Mfr_Name: MURATA; Mfr_Part_Number: GRM155R71C104KA88D; TOL: 10%; Voltage: 16V
J1 = SMA-END_PLUG_ROUND: Mfr_Name: Johnson Components; Mfr_Part_Number: 142-0711-821; TI_Silktext: AIN
J5 = SMA-END_PLUG_ROUND: Mfr_Name: Johnson Components; Mfr_Part_Number: 142-0711-821; TI_Silktext: DIN
J17 = SMA-END_PLUG_ROUND: Mfr_Name: Johnson Components; Mfr_Part_Number: 142-0711-821; TI_Silktext: BIN
J18 = SMA-END_PLUG_ROUND: Mfr_Name: Johnson Components; Mfr_Part_Number: 142-0711-821; TI_Silktext: CIN
R2 R6 R8 R12 R141 R142 R153 R154 = Res_0201_H: Mfr_Name: Vishay; Mfr_Part_Number: CRCW04024R99FKED; TOL: 1%; Wattage: 1/16W
R3 R5 R9 R11 R143 R144 R155 R156 = RES0603: GROUP: Not Installed; Mfr_Name: TE Connectivity; Mfr_Part_Number: 9-1879212-8; TOL: .1%; Wattage: 1/16W
R63 R101 R107 R119 R145 R146 R157 R158 = Res_0402_Zero: Mfr_Name: TE CONNECTIVITY; Mfr_Part_Number: 9-1879212-8
T1-T4 T6-T9 = XFMR_6_ADT2-1T+_2: Mfr_Name: Coilcraft
C16-C24 C35-C41 C53 C160 C161 C170-C172 C291 C292 = CAP0402_0: Mfr_Name: MURATA; Mfr_Part_Number: GRM033R61A104KE15D; TOL: 10%; Voltage: 16V
C25 C26 C78 C113 = CAP0402_0: Mfr_Name: TDK; Mfr_Part_Number: C0603X5R1A103K030BA; TOL: +/-10%; Voltage: 10V
C27-C33 = CAP_0201_0.1uF: Mfr_Name: MURATA; Mfr_Part_Number: GRM033R61A104KE15D; TOL: 10%; Voltage: 16V
C34 = CAP_0201_0.1uF: Mfr_Name: MURATA; Mfr_Part_Number: GRM033R61A104KE15D; TOL: 10%; Voltage: 10V
C43 = CAP_NP_0: Mfr_Name: AVX; Mfr_Part_Number: 06035C103JAT2A; TOL: 5%; VOLTAGE: 50V
C47 C48 = CAP0402_0: Mfr_Name: MURATA; Mfr_Part_Number: GRM033R61A104KE15D; TOL: 10%; Voltage: 10V
C190-C193 = CAP0402_0: Mfr_Name: MURATA; Mfr_Part_Number: GRM033R61A104KE15D; Note: DNI; TOL: 10%; Voltage: 10V
J6 = SMA-END_PLUG_ROUND: Mfr_Name: Johnson Components; Mfr_Part_Number: 142-0711-821; TI_Silktext: EXT_ADC_CLK
J21 = HEADER_1x2_100: TI_SILKTEXT: TRDYAB
J22 = HEADER_1x2_100: TI_SILKTEXT: TRDYCD
J23 = HEADER_1x2_100: TI_SILKTEXT: TRIGAB
J24 = HEADER_1x2_100: TI_SILKTEXT: TRIGCD
JP7 = SMD_JUMPER_1x3: Mfr_Name: SAMTEC; Mfr_Part_Number: HTSW-103-07-G-S; Note: SHUNT 2-3; TI_Silktext: PDN
R18 = R_1: CLASS: DISCRETE; Mfr_Name: PANASONIC; Mfr_Part_Number: ERJ-2RKF1001X; TOL: 1%; VOLTAGE: 1/10W
R19 R60 R61 = Res_0402_Zero_DNI
R20 R36 R134 = R_1: CLASS: DISCRETE; Mfr_Name: PANASONIC; Mfr_Part_Number: ERJ-2RKF1002X; TOL: 1%; VOLTAGE: 1/10W
R23 = RES0603: Mfr_Name: PANASONIC; Mfr_Part_Number: ERJ-2RKF1001X; TOL: 1%
R30 R31 = Res_0402_Zero_H_DNI: Mfr_Part_Number: ERJ-1GN0R00C
R34 R182 = Res_0201_200_H: Mfr_Part_Number: ERJ-1GEF1000C; Note: DNI; TOL: 1%
R35 R39 R185 R186 = Res_0402_Zero_H_DNI: Mfr_Part_Number: ERJ-1GN0R00C; Note: DNI
R133 = Res_0201_200_H: Mfr_Part_Number: ERJ-1GEF1000C; TOL: 1%
R59 R102 R170 R173 = Res_0402_49.9: Mfr_Part_Number: ERJ-2RKF49R9X; TOL: 1%
R183 R184 = Res_0201_200_H: Mfr_Part_Number: ERJ-1GEF3000C
SW1 = SPST_EVQ-PJ: Mfr_Part_Number: EVQ-PNF04M; TI_SILKTEXT: ADC_RESET
T5 = TFMR_6_TCM2-33X+
TP20 = T_POINT_R: Mfr_Name: KEYSTONE; Mfr_Part_Number: 5002; TI_SILK: SCAN_EN
U1 = ADS58J66_2: Mfr_Name: Texas Instruments; Mfr_Part_Number: ADS54J66, ADS58J63, ADS58J66
Z_SH-J38 = SHUNT-JUMPER: Mfr_Name: TE CONNECTIVITY; Mfr_Part_Number: 382811-8; Note: SHUNT FOR HEADER
C60 C82 C91 C99 = CAP_NP_0: Mfr_Name: MURATA; Mfr_Part_Number: GRM155R71C104KA88D; TOL: 10%
C65 = CAP_NP_0: Mfr_Name: MURATA; Mfr_Part_Number: GRM155F50J684ZE01D; TOL: 10%
C66 = CAP_NP_0: Mfr_Name: MURATA; Mfr_Part_Number: GRM155R71H392KA01D; TOL: 5%; VOLTAGE: 50V
C67 C68 C70-C73 C79 C86 C88 C89 C121 C152-C156 C162 C165 C166 = CAPACITOR_NP_1: Mfr_Name: MURATA; Mfr_Part_Number: GRM155R71C104KA88D; TOL: 10%; Voltage: 16V
C69 = CAP_NP_0: Mfr_Name: MURATA; Mfr_Part_Number: GRM1555C1H470FA01D; TOL: 1%; VOLTAGE: 50V
C80 C90 C122 C169 = CAP_0402_0.1uF_H: Mfr_Part_Number: GRM155R71C104KA88D; TOL: 10%; Voltage: 16V
C81 C94 = CAP_0603_100pF_H
C84 = CAP_0402_2200pF_H: Mfr_Name: MURATA; Mfr_Part_Number: GRM155R71E222KA01D
C85 = CAP_0402_10pF_H: Mfr_Part_Number: GRM1555C1H100JA01D
C87 = CAP_NP_2: CLASS: DISCRETE; Mfr_Name: TDK; Mfr_Part_Number: C1608X5R1C106M080AB; TOL: 10%; VOLTAGE: 16V
C92 = CAP_NP_0: Mfr_Name: MURATA; Mfr_Part_Number: GRM155R71C104KA88D_DNI; Note: DNI; TOL: 10%
C175 = CAP_0402_0.1uF_H: Mfr_Part_Number: GRM155R71C104KA88D_DNI; Note: DNI; TOL: 10%; Voltage: 16V
D3 = LED: Mfr_Name: LITE ON; Mfr_Part_Number: LTST-C150KGKT; TI_Silktext: PLL2 LOCKED
D4 = LED: Mfr_Name: LITE ON; Mfr_Part_Number: LTST-C150KGKT; TI_Silktext: CLKIN 0 SEL
D5 = LED: Mfr_Name: LITE ON; Mfr_Part_Number: LTST-C150KGKT; TI_Silktext: CLKIN 1 SEL
D6 = LED: Mfr_Name: LITE ON; Mfr_Part_Number: LTST-C150KGKT; TI_Silktext: PLL1 LOCKED
FB1-FB9 FB11 FB12 FB15 FB16 = FERRITE_BEAD_0402_H: Isat: 500mA; Mfr_Name: MURATA; Mfr_Part_Number: BLM31PG121SN1L
J10 = SMP_PLUG_SMT: Mfr_Name: MOLEX INC.; Mfr_Part_Number: 0853050232_DNI; Note: DNI; TI_Silktext: LMK_SYNC
J12 = SMA-THVT_142-0701-201_REC: TI_Silktext: CLKIN
JP2 = SMD_JUMPER_1x2: Mfr_Name: SAMTEC; Mfr_Part_Number: HTSW-102-08-G-S; Note: SHUNT 1-2; TI_Silktext: XO_PWR
R21 R40 R43 R44 = Res_0402_249: Mfr_Part_Number: ERJ-2RKF2400X
R62 R108 R109 = Res_0402_Zero_H
R65 = R_1: CLASS: DISCRETE; Mfr_Name: PANASONIC; Mfr_Part_Number: ERJ-2GEJ621X; TOL: 1%
R66 = R_1: CLASS: DISCRETE; Mfr_Name: PANASONIC; Mfr_Part_Number: ERJ-2GEJ393X; TOL: 1%
R71 R88 = Res_0402_100_H
R73 R78 = RESISTOR_0: CLASS: DISCRETE; Mfr_Name: DALE; Mfr_Part_Number: CRCW0603130RFKEA_DNI; Note: DNI; TOL: 1%; Wattage: 1/10W
R74 R87 = RESISTOR_0: CLASS: DISCRETE; Mfr_Name: DALE; Mfr_Part_Number: CRCW060382R0FKEA_DNI; Note: DNI; TOL: 1%; Wattage: 1/10W
R77 R100 = Res_0402_49.9: TOL: 1%
R79 R80 R105 R106 = Res_0402_249: Mfr_Part_Number: ERJ-2RKF2400X_DNI; Note: DNI
R81 R82 R85 R86 R91 = RESISTOR_0: CLASS: DISCRETE; Mfr_Name: DALE; Mfr_Part_Number: CRCW0603750RFKEA
R104 = Res_0402_49.9: Mfr_Part_Number: ERJ-2RKF49R9X_DNI; Note: DNI; TOL: 1%
SJP1 = JUMPER_SMD_L_0603: TI_Silktext: EN
U5 = LMK04828_0: Mfr_Name: TI; Mfr_Part_Number: LMK04828BISQ/NOPB
Y1 = OSC_SM_6_TCO-2100-SERIES_2: Mfr_Name: Crystek; Mfr_Part_Number: CVHD-950-122.880
Z_SH-J7 = SHUNT-JUMPER: Mfr_Name: TE CONNECTIVITY; Mfr_Part_Number: 382811-8; Note: SHUNT FOR HEADER; TI_SILK: SHUNT 1-2
C50 C57 = CAPACITOR_NP_1: Mfr_Name: TDK; Mfr_Part_Number: C1005X5R1C105K050BC; TOL: 10%; Voltage: 16V
C51 C58 = CAPACITOR_POL_0: Mfr_Name: KEMET; Mfr_Part_Number: T520B106M016ATE100; Note: LOW ESR/OR EQUIVALENT; TOL: 20%; VOLTAGE: 16V
C52 C56 C59 C61-C64 = CAPACITOR_NP_1: Mfr_Name: MURATA; Mfr_Part_Number: GRM155R71H103KA88D; TOL: 10%; Voltage: 16V
C100-C102 C164 C173 C174 = CAP_0402_1uF: Mfr_Name: TDK; Mfr_Part_Number: C1005X5R1C105K050BC
D1 = LED: Mfr_Name: LITE ON; Mfr_Part_Number: LTST-C150KGKT; TI_Silktext: JESD_SYNC
J3 = CON_SMVT_40X10_ASP-134487-01: Mfr_Part_Number: SEAM-40-02.0-S-10-2-A-K-TR
R84 = Res_0402_Zero: Mfr_Part_Number: ERJ-2GE0R00X_DNI; Note: DNI
C93 C95 = CAP0603: CLASS: DISCRETE; Mfr_Name: MURATA; Mfr_Part_Number: GRM1555C1H470FA01D; Note: DNI; TOL: 1%; VOLTAGE: 50V
C163 = CAP_TANT_B_4.7uF_10V: Mfr_Part_Number: TAJB475K010RNJ
FB10 = FERRITE_BEAD_0402_H: Mfr_Name: MURATA; Mfr_Part_Number: BLM41PG102SN1L
J13 = USB_MINI_AB_MNE20-5G5P10: Mfr_Name: WURTH ELEKTRONIK; Mfr_Part_Number: 651305142821; TI_SILKTEXT: USB I/F ADC/LMK
R13 = R: Mfr_Name: PANASONIC; Mfr_Part_Number: ERJ-3GEY0R00V; TOL: 5%
R96 = Res_0603_Zero_DNI: Note: DNI
TP21 = TESTPOINT_BLUE: Mfr_Part_Number: 5000; TI_SILKTEXT: 5V_USB
U7 = FT245RL: Mfr_Name: FTDI Chip; Mfr_Part_Number: FT245RL-REEL
J15 = HEADER_2x5_100: Mfr_Part_Number: HTSW-105-07-G-D; TI_SILKTEXT: PROG
J25 = HEADER_1x4_0: TI_SILKTEXT: SPI
JP3 = Jumper_1x3_100_0: Mfr_Name: SAMTEC; Mfr_Part_Number: HTSW-103-07-G-S; Note: SHUNT 2-3; TI_Silktext: SPI_SELECTOR
R57 = R_0: Mfr_Name: PANASONIC; Mfr_Part_Number: ERJ-2RKF1001X; TOL: 1%
R110 = R_0: Mfr_Name: PANASONIC; Mfr_Part_Number: ERJ-2RKF1001X; PART_NUMBER: Panasonic ERJ-2RKF1001X; TOL: 1%
R111 = R_0: CLASS: DISCRETE; Mfr_Name: PANASONIC; Mfr_Part_Number: ERJ-2RKF1002X; TOL: 1%
R76 R113 = R: Mfr_Name: PANASONIC; Mfr_Part_Number: ERJ-2GE0R00X_DNI; Note: DNI; TOL: 5%
U3 = ALTERA_5M80ZT100
Z_SH-H4 = SHUNT-HEADER: Mfr_Name: TE CONNECTIVITY; Mfr_Part_Number: 382811-8
C96 C97 C125 = CAP_1210_22uF: Mfr_Name: TDK; Mfr_Part_Number: C3225X5R1A226M230AA; TOL: 20%; VOLTAGE: 10V
C103 = CAP_POL-B: Mfr_Name: AVX; Mfr_Part_Number: TPSB476K010R0250; TOL: 10%
C104 C105 C109 C126 C149 C182 C263 C285 C288 C289 = CAP_NP_1: Mfr_Name: MURATA; Mfr_Part_Number: GRM21BR61E106KA73L; TOL: 10%; VOLTAGE: 25V
C106 C114 C129 C134 C137 C183 C286 C287 = CAP_0603_.47uF: Mfr_Part_Number: 0603YD474KAT2A
C98 C108 C128 C139 C147 C151 C282 C284 = CAP_NP_0: Mfr_Name: TDK; Mfr_Part_Number: C1608X7R1E105K080AB; TOL: 10%; VOLTAGE: 25V
C75 C110 C130 C142 C279 = CAP_POL-B: Mfr_Name: AVX; Mfr_Part_Number: TPSB336K016R0350; TOL: 10%; Voltage: 10V
C83 C111 C143 C278 = CAP0201_0: Mfr_Name: MURATA; Mfr_Part_Number: GRM21BR61E106KA73L; TOL: 20%; VOLTAGE: 6.3V
C118 C195 = CAP_1206_2.2uF: CLASS: DISCRETE; Mfr_Part_Number: GRM31CR61E106KA12L; TOL: 10%; VOLTAGE: 16V
C76 C119 C123 C148 = CAP_TANT_B_4.7uF_10V: Mfr_Part_Number: TAJB475K010RNJ_DNI; Note: DNI
C120 C124 = CAP_0603_0.1uF: Mfr_Name: MURATA; Mfr_Part_Number: GRM188R71C104KA01D; TOL: 10%; Voltage: 16V
C131 = CAP0201_0: Mfr_Name: MURATA; Mfr_Part_Number: GRM21BR61E106KA73L; TOL: 20%; VOLTAGE: 25V
C132 C145 C281 = CAP_NP_1: Mfr_Name: TDK; Mfr_Part_Number: C1608X7R1E105K080AB; TOL: 10%; VOLTAGE: 25V
C135 = CAP_0603_3300pF: Mfr_Part_Number: 06035C332KAT2A_DNI; Note: DNI
C136 = CAP_0603_.01uF_25V_X7R_10%: Mfr_Name: AVX; Mfr_Part_Number: 06035C103JAT2A; VOLTAGE: 50V
C144 C194 C196-C198 C272 C273 = CAP_0603_3300pF
D2 = LED_GREEN_1206: TI_SILKTEXT: PWR
F1 = FUSE_0: Mfr_Name: TE Connectivity; Mfr_Part_Number: 1206SFF200F/63-2_DNI; Note: DNI
FB13 FB14 FB17 = BEAD_NFM31P: Mfr_Name: Murata; Mfr_Part_Number: NFM31PC276B0J3; Tolerance: 20%
J14 = CONN_JACK_PWR: Mfr_Name: SWITCHCRAFT; Mfr_Part_Number: RAPC722X
L1 = INDUCTOR-1: Mfr_Name: COILCRAFT; Mfr_Part_Number: MSS1048-152NL
Q1 = CSD18532Q5B
R41 = Res_0402_1k: TOL: 1%
R45 = Res_0603_12.4k: Mfr_Part_Number: ERA-2AEB1372X
R47 R175 = Res_0603_12.4k: Mfr_Part_Number: ERJ-2RKF2000X
R48 R116 R124 R181 = Res_0603_10k: Mfr_Part_Number: RA-2AEB103X
R50 R123 = Res_0603_12.4k: Mfr_Part_Number: ERA-2AEB392X
R51 = Res_0603_665K
R52 = Res_0603_7.68K
R112 = Res_0603_Zero_DNI: Mfr_Part_Number: ERJ-3GEY0R00V
R114 R126 R162 R167 R178 R189 = Res_0603_Zero_DNI
R115 R118 = Res_0603_100k
R117 = Res_0603_10k: Mfr_Part_Number: ERJ-3EKF4872V
R125 R161 R166 R177 R187 R188 = Res_0603_Zero
R174 R176 = Res_0603_12.4k: Mfr_Part_Number: ERJ-2RKF4990X
R180 = Res_0603_12.4k: Mfr_Part_Number: ERJ-2RKF1272X
TP7-TP11 TP25-TP27 = TESTPOINT_BLK
TP14 TP22 = TESTPOINT_BLUE: Mfr_Part_Number: 5000; TI_SILKTEXT: DRVDD1.15V
TP15 = TESTPOINT_BLUE: Mfr_Part_Number: 5000; TI_SILKTEXT: AVDD1.15V
TP16 = TESTPOINT_BLUE: Mfr_Part_Number: 5000; TI_SILKTEXT: 5.0V
TP18 = TESTPOINT_BLUE: Mfr_Part_Number: 5000; TI_SILKTEXT: 2.5V
TP19 = TESTPOINT_BLUE: Mfr_Part_Number: 5000; TI_SILKTEXT: AVDD1.9V
TP23 = TESTLOOP_BLACK: Mfr_Name: Keystone; Mfr_Part_Number: 5010; TI_SILKTEXT: +5V
TP24 = TESTLOOP_BLACK: Mfr_Name: KEYSTONE; Mfr_Part_Number: 5011; TI_SILKTEXT: GND
U2 U10 U11 U16 = TPS7A8101
U8 = TPS54319RTE
U12 = TPS2400: Mfr_Name: Texas Instruments; Mfr_Part_Number: TPS2400DBVT
C74 = CAP_NP_0: Mfr_Name: MURATA; Mfr_Part_Number: GRM31CR61A476ME15L; TOL: 20%; VOLTAGE: 10V
C115 C184 = CAP_NP_0: Mfr_Name: YAGEO; Mfr_Part_Number: CC0603KRX7R7BB105; TOL: 10%; VOLTAGE: 16V
C116 = CAP_0603_0.01uF: Mfr_Name: AVX; Mfr_Part_Number: 06035C103JAT2A; VOLTAGE: 50V
C117 = CAP_NP_0: CLASS: DISCRETE; Mfr_Name: MURATA; Mfr_Part_Number: GRM21BR71A106KE51L; TOL: 10%; VOLTAGE: 10V
C185 = CAP_0603_2.2uF: Mfr_Part_Number: GRM21BR71A106KE51L; TOL: 10%; VOLTAGE: 10V
C265 = CAP_NP_2: Mfr_Name: MURATA; Mfr_Part_Number: GRM155R71C153KA01D; TOL: 10%; VOLTAGE: 16V
C271 = CAP_1210_150uF_6.3V
L2 = INDUCTOR-1: Mfr_Name: N/A; Mfr_Part_Number: N/A
L3 = INDUCTOR-1: Mfr_Name: N/A; Mfr_Part_Number: N/A; Note: DNI
L4 = INDUCTOR-1: Mfr_Name: COILCRAFT; Mfr_Part_Number: XFL4020-102MEB
MT1-MT6 = MOUNTING_HOLE: Mfr_Name: RAF; Mfr_Part_Number: 1648-440-AL
R28 R29 = Res_0603_Zero_DNI: Mfr_Part_Number: ERJ-2GE0R00X
R32 = Res_0603_162K
R33 = Res_0603_10
R37 = Res_0603_80.6K
R64 = Res_0603_634: Mfr_Part_Number: ERA-2AEB202X
R72 = R: Mfr_Name: PANASONIC; Mfr_Part_Number: ERJ-2GE0R00X; TOL: 1%
R75 R83 = R: Mfr_Name: PANASONIC; Mfr_Part_Number: ERJ-2GE0R00X; TOL: 5%
R128 = Res_0603_4.99K: Mfr_Part_Number: ERA-2AEB4991X
R129 = Res_0603_Zero: Mfr_Part_Number: ERJ-6GEY0R00V
TP1 = TESTPOINT_BLUE: Mfr_Part_Number: 5000; TI_SILKTEXT: +3.3VCLK
TP2 = TESTPOINT_GRN: Mfr_Part_Number: 5000; TI_SILKTEXT: IOVDD1.15V
U6 = TPS7A4700: Mfr_Name: Texas Instruments; Mfr_Part_Number: TPS7A4700RGWT
U9 = TPS74201_QFN20: Mfr_Name: Texas Instruments; Mfr_Part_Number: TPS74201RGWR
U15 = TPS62085
Z_BOARD1 = BARE_BOARD: Mfr_Part_Number: ADS5XJ6X REV A
Z_SCREW1-Z_SCREW6 = STANDOFF-SCREW: Mfr_Part_Number: PMSSS 440 0075 PH; Note: SCREW FOR STANDOFF

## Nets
5.0V_IN: F1.1 J14.1 Q1.5(D5) Q1.6(D6) Q1.7(D7) Q1.8(D8) TP23.1(TP) U12.5(VIN)
5VIN: C103.1 C104.1 C118.1 C119.1 C120.1 C149.1 C194.1 F1.2 L2.1 Q1.1(S1) Q1.2(S2) Q1.3(S3) R41.1 R96.1 R112.1 R118.2 TP16.1(TP) U6.13(EN) U6.15(IN2) U6.16(IN1) U8.1(VIN2) U8.2(VIN3) U8.16(VIN1)
+2.5V: C96.2 C97.2 C105.1 C125.2 C126.1 C185.1 C288.1 C289.1 L1.2 R115.2 R125.1 R161.1 R166.1 R177.1 R187.1 R188.1 TP18.1(TP) U2.7(IN2) U2.8(IN1) U9.5(IN1) U9.6(IN2) U9.7(IN3) U9.8(IN4) U10.7(IN2) U10.8(IN1) U11.7(IN2) U11.8(IN1) U16.7(IN2) U16.8(IN1)
+3.3VCLK: C56.1 C61.1 C62.1 C63.1 C64.1 C75.1 C77.1 C78.1 C83.1 C152.2 C153.2 C154.2 FB1.1 FB2.1 FB5.1 FB6.1 FB7.1 FB8.1 FB9.1 FB16.2 JP2.2 R73.1 R78.1 R134.1 SJP1.1(Pin1) TP1.1(TP) U3.59(VCCIO2) U3.80(VCCIO2) U3.94(VCCIO2)
AVDD1.9V: C23.1 C24.1 C25.1 C26.1 C110.1 C111.1 C112.1 C113.1 C160.1 C161.1 FB15.2 JP7.1(Pin1) R18.1 R19.1 R23.1 R183.2 TP19.1(TP) U1.10(AVDD19V) U1.16(AVDD19V) U1.24(AVDD19V) U1.31(AVDD19V) U1.39(AVDD19V) U1.45(AVDD19V)
AVDD1.15V: C20.1 C21.1 C35.1 C36.1 C37.1 C38.1 C39.1 C40.1 C41.1 C130.1 C131.1 C132.1 C133.1 C171.1 C172.1 C291.1 C292.1 FB13.3 TP15.1(TP) U1.9(AVDD) U1.12(AVDD) U1.15(AVDD) U1.17(AVDD) U1.20(AVDD) U1.25(AVDD) U1.30(AVDD) U1.35(AVDD) U1.38(AVDD) U1.40(AVDD) U1.43(AVDD) U1.44(AVDD) U1.46(AVDD)
GND: C2.2 C4.1 C5.1 C8.2 C10.1 C11.1 C16.2 C17.2 C18.2 C19.2 C20.2 C21.2 C22.2 C23.2 C24.2 C25.2 C26.2 C35.2 C36.2 C37.2 C38.2 C39.2 C40.2 C41.2 C49.2 C50.2 C51.2 C52.2 C53.2 C56.2 C57.2 C58.2 C59.2 C60.2 C61.2 C62.2 C63.2 C64.2 C69.2 C74.2 C75.2 C76.2 C77.2 C78.2 C79.1 C81.1 C83.2 C84.1 C85.1 C87.2 C88.2 C90.1 C91.2 C93.2 C94.1 C95.2 C96.1 C97.1 C98.2 C99.2 C100.2 C101.2 C102.2 C103.2 C104.2 C105.2 C107.2 C108.2 C109.2 C110.2 C111.2 C112.2 C113.2 C114.2 C115.2 C116.2 C117.2 C118.2 C119.2 C120.2 C121.1 C123.2 C125.1 C126.2 C127.2 C128.2 C130.2 C131.2 C132.2 C133.2 C134.2 C135.2 C136.2 C138.2 C139.2 C142.2 C143.2 C144.2 C145.2 C146.2 C147.2 C148.2 C149.2 C150.2 C151.2 C152.1 C153.1 C154.1 C155.1 C156.1 C160.2 C161.2 C162.1 C163.2 C164.2 C165.1 C166.1 C170.2 C171.2 C172.2 C173.2 C174.2 C182.2 C183.2 C184.2 C185.2 C194.2 C195.2 C197.2 C198.2 C200.1 C201.2 C204.1 C205.1 C206.2 C263.2 C265.2 C271.2 C272.2 C273.2 C277.1 C278.2 C279.2 C280.2 C281.2 C282.2 C283.2 C284.2 C285.2 C286.2 C288.2 C289.2 C290.2 C291.2 C292.2 D1.2(CATHODE) D2.2(CATHODE) D3.2(CATHODE) D4.2(CATHODE) D5.2(CATHODE) D6.2(CATHODE) FB13.2 FB14.2 FB17.2 J1.2(SHIELD3) J1.3(SHIELD4) J1.4(SHIELD1) J1.5(SHIELD2) J3.A1 J3.A4 J3.A5 J3.A8 J3.A9 J3.A12 J3.A13 J3.A16 J3.A17 J3.A20 J3.A21 J3.A24 J3.A25 J3.A28 J3.A29 J3.A32 J3.A33 J3.A36 J3.A37 J3.A40 J3.B2 J3.B3 J3.B6 J3.B7 J3.B10 J3.B11 J3.B14 J3.B15 J3.B18 J3.B19 J3.B22 J3.B23 J3.B26 J3.B27 J3.B30 J3.B31 J3.B34 J3.B35 J3.B38 J3.B39 J3.C1 J3.C4 J3.C5 J3.C8 J3.C9 J3.C12 J3.C13 J3.C16 J3.C17 J3.C20 J3.C21 J3.C24 J3.C25 J3.C28 J3.C29 J3.C32 J3.C33 J3.C36 J3.C38 J3.C40 J3.D2 J3.D3 J3.D6 J3.D7 J3.D10 J3.D13 J3.D16 J3.D19 J3.D22 J3.D25 J3.D28 J3.D37 J3.D39 J3.E1 J3.E4 J3.E5 J3.E8 J3.E11 J3.E14 J3.E17 J3.E20 J3.E23 J3.E26 J3.E29 J3.E32 J3.E35 J3.E38 J3.E40 J3.F2 J3.F3 J3.F6 J3.F9 J3.F12 J3.F15 J3.F18 J3.F21 J3.F24 J3.F27 J3.F30 J3.F33 J3.F36 J3.F39 J3.G1 J3.G4 J3.G5 J3.G8 J3.G11 J3.G14 J3.G17 J3.G20 J3.G23 J3.G26 J3.G29 J3.G32 J3.G35 J3.G38 J3.G40 J3.H3 J3.H6 J3.H9 J3.H12 J3.H15 J3.H18 J3.H21 J3.H24 J3.H27 J3.H30 J3.H33 J3.H36 J3.H39 J3.J1 J3.J4 J3.J5 J3.J8 J3.J11 J3.J14 J3.J17 J3.J20 J3.J23 J3.J26 J3.J29 J3.J32 J3.J35 J3.J38 J3.J40 J3.K2 J3.K3 J3.K6 J3.K9 J3.K12 J3.K15 J3.K18 J3.K21 J3.K24 J3.K27 J3.K30 J3.K33 J3.K36 J3.K39 J5.2(SHIELD3) J5.3(SHIELD4) J5.4(SHIELD1) J5.5(SHIELD2) J6.2(SHIELD3) J6.3(SHIELD4) J6.4(SHIELD1) J6.5(SHIELD2) J10.2(SHIELD1) J12.2(GND) J12.3(GND) J12.4(GND) J12.5(GND) J13.5(GND) J13.6(GND1) J13.7(GND2) J13.8(GND3) J13.9(GND4) J14.2 J14.3 J15.2 J15.10 J17.2(SHIELD3) J17.3(SHIELD4) J17.4(SHIELD1) J17.5(SHIELD2) J18.2(SHIELD3) J18.3(SHIELD4) J18.4(SHIELD1) J18.5(SHIELD2) J21.2 J22.2 J23.2 J24.2 JP3.3(Pin3) JP7.3(Pin3) MT1.1 MT2.1 MT3.1 MT4.1 MT5.1 MT6.1 R13.1 R20.2 R21.2 R29.2 R32.2 R36.2 R40.2 R43.2 R44.2 R48.2 R51.2 R57.2 R59.2 R65.2 R66.2 R72.1 R74.2 R75.1 R76.1 R77.2 R79.2 R80.2 R83.1 R84.2 R87.2 R100.2 R102.2 R104.2 R105.2 R106.2 R114.2 R116.2 R117.2 R124.2 R126.2 R128.2 R162.2 R167.2 R170.2 R173.2 R178.2 R181.2 R184.1 R189.2 SJP1.3(Pin3) T1.6(primary_ct) T3.6(primary_ct) T6.6(primary_ct) T8.6(primary_ct) TP7.1(TP) TP8.1(TP) TP9.1(TP) TP10.1(TP) TP11.1(TP) TP24.1(TP) TP25.1(TP) TP26.1(TP) TP27.1(TP) U1.3(DGND) U1.21(AGND) U1.26(AGND) U1.29(AGND) U1.32(AGND) U1.52(DGND) U1.60(DGND) U1.63(DGND) U1.67(DGND) U1.73(PAD) U2.4(GND) U2.9(PAD) U3.1(GND) U3.10(GND) U3.11(GND) U3.32(GND) U3.46(GND) U3.60(GND) U3.65(GND) U3.79(GND) U3.93(GND) U5.65(DAP) U6.7(GND) U6.21(PWRPAD) U7.7(GND) U7.18(GND) U7.21(GND) U7.25(AGND) U7.26(TEST) U8.3(GND1) U8.4(GND2) U8.5(AGND) U8.17(PWRPAD) U9.2(NC1) U9.3(NC2) U9.4(NC3) U9.12(GND) U9.13(NC4) U9.14(NC5) U9.17(NC6) U9.21(PWRPAD) U10.4(GND) U10.9(PAD) U11.4(GND) U11.9(PAD) U12.2(GND) U15.5(GND) U16.4(GND) U16.9(PAD) Y1.3(GND)
VCC1_VCC5_VCC6: C50.1 C51.1 C52.1 FB1.2 U5.10(VCC1_VCO) U5.33(VCC5_DIG) U5.36(VCC6_PLL1)
VCC2_CG1: C174.1 FB5.2 U5.17(VCC2_GC1)
VCC3_SYSREF: C173.1 FB6.2 U5.21(VCC3_SYSREF)
VCC4_CG2: C102.1 FB7.2 U5.26(VCC4_CG2)
VCC7_OSCOUT: FB3.2 U5.39(VCC7_OSCout)
VCC8_OSCIN: FB11.2 U5.42(VCC8_OSCin)
VCC8_VCC10: C57.1 C58.1 C59.1 FB2.2 FB3.1 FB4.1 FB11.1 U5.47(VCC10_PLL2)
VCC9_CP2: C164.1 FB4.2 U5.45(VCC9_CP2)
VCC11_CG3: C101.1 FB8.2 U5.53(VCC11_CG3)
VCC12_CG0: C100.1 FB9.2 U5.64(VCC12_CG0)
AAINM: T1.3(secondary_dot) T2.1(secondary_ct)
AAINP: T1.1(secondary_ct) T2.3(secondary_dot)
ACLK_N: C48.1 C193.2 R34.2 R39.2 U1.28(CLKIN_M)
ACLK_P: C47.1 C192.2 R34.1 R35.2 U1.27(CLKIN_P)
ACLKN: R39.1 T5.3(secondary)
ACLKP: R35.1 T5.4(secondary_dot)
ADC_CLK: C43.1 J6.1(CENTER)
ADC_SCLK: J25.1 U1.6(SCLK) U3.33(IO_1_33/DIFFIO_B3N)
ADC_SDIO: J25.3 U1.5(SDIN) U3.35(IO_1_35/DIFFIO_B4N)
ADC_SDO: J25.4 U1.11(SDOUT) U3.36(IO_1_36/DIFFIO_B5P)
ADC_SEN: J25.2 R23.2 U1.7(SEN) U3.34(IO_1_34/DIFFIO_B4P)
ADCCLK: C43.2 T5.6(primary_dot)
AIN+: J1.1(CENTER) T1.4(primary_dot)
AINM: R6.2 R63.1 U1.41(INA_M)
AINP: R2.2 R101.2 U1.42(INA_P)
BBINM: T6.3(secondary_dot) T7.1(secondary_ct)
BBINP: T6.1(secondary_ct) T7.3(secondary_dot)
BIN: J17.1(CENTER) T6.4(primary_dot)
BINM: R142.2 R146.2 U1.37(INB_M)
BINP: R141.2 R145.1 U1.36(INB_P)
CCINM: T8.1(secondary_ct) T9.3(secondary_dot)
CCINP: T8.3(secondary_dot) T9.1(secondary_ct)
CIN: J18.1(CENTER) T8.4(primary_dot)
CINM: R153.2 R157.1 U1.18(INC_M)
CINP: R154.2 R158.2 U1.19(INC_P)
CLK_IN: C122.1 R62.2 R100.1
CLK_LAO_0M: C86.1 J3.G7
CLK_LAO_0P: C89.1 J3.G6
CLK_N: C71.1 R40.1 U5.16(DCLKOUT2n)
CLK_P: C70.1 R21.1 U5.15(DCLKOUT2p)
CLKIN: J12.1(CENTER) R60.1 R62.1
CLKIN1N: C79.2 C175.2 U5.35(CLKIN1n/FBCLKINn/FINn)
CLKIN1P: C122.2 U5.34(CLKIN1p/FBCLKINp/FINp)
CLKLA_0N: C89.2 R80.1 U5.63(DCLKOUT12n)
CLKLA_0P: C86.2 R79.1 U5.62(DCLKOUT12p)
CLKM: C48.2 C70.2
CLKP: C47.2 C71.2
CP1: C60.1 C65.1 C94.2 U5.32(CPOUT1) Y1.1(VC)
CP2: C66.1 C69.1 U5.46(CPOUT2)
DA_M: C28.1 U1.59(DAM)
DA_P: C27.1 U1.58(DAP)
DAM: C28.2 J3.A11
DAP: C27.2 J3.A10
DB_M: C30.1 U1.62(DBM)
DB_P: C29.1 U1.61(DBP)
DBM: C30.2 J3.A7
DBP: C29.2 J3.A6
DC_M: C32.1 U1.65(DCM)
DC_P: C31.1 U1.66(DCP)
DCM: C32.2 J3.A3
DCP: C31.2 J3.A2
DD_M: C34.1 U1.68(DDM)
DD_P: C33.1 U1.69(DDP)
DDINM: T3.1(secondary_ct) T4.3(secondary_dot)
DDINP: T3.3(secondary_dot) T4.1(secondary_ct)
DDM: C34.2 J3.C7
DDP: C33.2 J3.C6
DIN: J5.1(CENTER) T3.4(primary_dot)
DINM: R8.2 R119.2 U1.14(IND_M)
DINP: R12.2 R107.1 U1.13(IND_P)
DRVDD1.15V: C16.1 C17.1 C142.1 C143.1 C145.1 C146.1 C147.1 FB14.3 TP14.1(TP) U1.8(DVDD) U1.47(DVDD)
FMC_CLK_N: C193.1 J3.K29
FMC_CLK_P: C192.1 J3.K28
FMC_D5: J3.G16 U3.7(IO_1_7/DIFFIO_L3N)
FMC_D6: J3.H16 U3.8(IO_1)
FMC_DIR_CONTROL: J3.H17 U3.15(IO_1)
FMC_SCLK: J3.C14 U3.2(IO_1_2/DIFFIO_L1P)
FMC_SDIO: J3.C15 U3.3(IO_1_3/DIFFIO_L1N)
FMC_SDO: J3.D14 U3.4(IO_1_4/DIFFIO_L2P)
FMC_SEN_ADC: J3.D15 U3.5(IO_1_5/DIFFIO_L2N)
FMC_SEN_LMK: J3.G15 U3.6(IO_1_6/DIFFIO_L3P)
FMC_SYSREF_N: C191.1 J3.K38
FMC_SYSREF_P: C190.1 J3.K37
FPGA_JESD_CLKM: C67.2 J3.D5
FPGA_JESD_CLKP: C68.2 J3.D4
FPGA_JESD_SYSREFM: J3.G10 R109.2
FPGA_JESD_SYSREFP: J3.G9 R108.2
FTDI_D5: U3.54(IO_2_54/DIFFIO_R7P) U7.9(D5)
FTDI_D6: U3.53(IO_2_53/DIFFIO_R7N) U7.10(D6)
FTDI_DIR_CONTROL: U3.52(IO_2) U7.6(D7)
FTDI_SCLK: U3.61(IO_2) U7.1(D0)
FTDI_SDIO: U3.58(IO_2_58/DIFFIO_R5P) U7.5(D1)
FTDI_SDO: U3.57(IO_2_57/DIFFIO_R5N) U7.3(D2)
FTDI_SEN_ADC: U3.56(IO_2_56/DIFFIO_R6P) U7.11(D3)
FTDI_SEN_LMK: U3.55(IO_2_55/DIFFIO_R6N) U7.2(D4)
IOVDD1.15V: C18.1 C19.1 C22.1 C53.1 C170.1 C272.1 C273.1 L3.2 R129.2 TP2.1(TP) U1.4(IOVDD) U1.51(IOVDD) U1.57(IOVDD) U1.64(IOVDD) U1.70(IOVDD)
JESD_CLKM: C68.1 U5.2(DCLKOUT0n)
JESD_CLKP: C67.1 U5.1(DCLKOUT0p)
JESD_SYSREFM: R108.1 U5.4(SDCLKOUT1n)
JESD_SYSREFP: R109.1 U5.3(SDCLKOUT1p)
LMK_CS: U3.78(IO_2_78/DIFFIO_T9P) U5.18(\\~{CS})
LMK_SCK: U3.77(IO_2_77/DIFFIO_T9N) U5.19(SCK)
LMK_SDIO: R134.2 U3.76(IO_2_76/DIFFIO_T10P) U5.20(SDIO)
LMK_SDO: R113.2 U5.5(RESET)
LMK_SYNC: J10.1(CENTER) R59.1 U5.6(SYNC)
OSCIN_N: C82.2 U5.44(OSCINn)
OSCIN_P: C92.2 C121.2 U5.43(OSCINp)
PDN: JP7.2(Pin2) U1.50(PDN)
RESET: R36.1 SW1.2 U1.48(RESET)
SCAN_EN: R19.2 R20.1 TP20.1(TP) U1.49(SCAN_EN)
SYNCbABM: J3.G13 U1.56(SYNCbABM)
SYNCbABP: J3.G12 U1.55(SYNCbABP)
SYNCbCDM: J3.H32 R185.2
SYNCbCDP: J3.H31 R186.2
SYSREF+: C190.2 R30.2 R133.1 U1.33(SYSREF_P)
SYSREF-: C191.2 R31.2 R133.2 U1.34(SYSREF_M)
SYSREF_N: C72.1 R44.1 U5.14(SDCLKOUT3n)
SYSREF_P: C73.1 R43.1 U5.13(SDCLKOUT3p)
SYSREFM: C73.2 R31.1 R106.1
SYSREFP: C72.2 R30.1 R105.1
T2_1: C141.2 R2.1 R3.1
T2_3: C140.2 R5.2 R6.1
T4_1: C158.2 R8.1 R9.1
T4_3: C157.2 R11.2 R12.1
T7_1: C274.2 R142.1 R144.1
T7_3: C275.2 R141.1 R143.2
T9_1: C203.2 R154.1 R155.1
T9_3: C202.2 R153.1 R156.2
TCK: J15.1 R57.1 U3.24(TCK)
TDI: J15.9 R110.1 U3.23(TDI)
TDO: J15.3 U3.25(TDO)
TMS: J15.5 R111.1 U3.22(TMS)
TRDYAB: J21.1 U1.54(TRDYAB)
TRDYCD: J22.1 U1.1(TRDYCD)
TRIGAB: J23.1 R170.1 U1.53(TRIGAB)
TRIGCD: J24.1 R173.1 U1.2(TRIGCD)
VCPLD1.8V: C155.2 C156.2 C162.2 C165.2 C166.2 C278.1 C279.1 C280.1 C281.1 C282.1 FB17.3 J15.4 JP3.1(Pin1) R110.2 R111.2 TP22.1(TP) U3.9(VCCIO1) U3.13(VCCINT) U3.31(VCCIO1) U3.45(VCCIO1) U3.63(VCCINT)
VSNS: R115.1 R117.1 U8.6(VSENSE)
N16275326: C10.2 T3.2(secondary) T3.5(primary)
N16275564: C11.2 T4.2(secondary) T4.5(primary)
N16918679: C81.2 C84.2 C85.2 C90.2 FB12.1 Y1.6(VDD)
N16918713: R78.2 R87.1 R88.1 Y1.5(OUT_P)
N16918734: R71.1 R73.2 R74.1 Y1.4(OUT_N)
N16918766: FB12.2 JP2.1
N16918796: C80.1 R71.2
N16918798: C80.2 C82.1 R77.1
N16918863: C92.1 C169.2 R61.2 R102.1
N16918987: SJP1.2(Pin2) Y1.2(NC)
N16974113: R113.1 U3.81(IO_2_81/DIFFIO_T8N)
N16976956: JP3.2(Pin2) U3.51(IO_1_51/DIFFIO_B10N)
N17045898: C169.1 R88.2
N17135362: C175.1 R104.1
N17316333: R60.2 R61.1
N17990226: C2.1 R3.2 R5.1
N18101124: Q1.4(G) U12.4(GATE)
N18135910: C106.1 C107.1 C108.1 C109.1 C148.1 FB15.1 R45.1 U11.1(OUT1) U11.2(OUT2)
N18153199: C95.1 J13.2(D-) U7.16(USBDM)
N18153225: C91.1 C163.1 FB10.1 R96.2 TP21.1(TP) U7.20(VCC)
N18153227: C99.1 U7.4(VCCIO) U7.17(3V3OUT)
N18153268: C93.1 J13.3(D+) U7.15(USBDP)
N18164060: J13.4(ID) R13.2
N18272382: C137.1 C138.1 C139.1 C182.1 FB14.1 R123.1 U2.1(OUT1) U2.2(OUT2)
N18340257: D2.1(ANODE) R41.2
N18400299: D1.1(ANODE) R91.1
N18433453: R112.2 R114.1 U8.15(EN)
N18433599: C135.1 R52.1 U8.7(COMP)
N18433651: C144.1 R52.2
N18433655: R51.1 U8.8(RT/CLK)
N18433661: C136.1 U8.9(SS/TR)
N18433720: R118.1 U8.14(PWRGD)
N18433762: C124.1 L1.1 U8.10(PH1) U8.11(PH2) U8.12(PH3)
N18433788: C124.2 U8.13(BOOT)
N18529139: J3.C18 R91.2
N18529232: J3.H2 R84.1
N18993446: C8.1 R9.2 R11.1
N19018410: R18.2 SW1.1
N19072087: FB10.2 J13.1(VBUS)
N19596618: D6.1(ANODE) R85.1
N19596621: D5.1(ANODE) R82.1
N19596623: D3.1(ANODE) R86.1
N19596624: R86.2 U5.48(STATUS_LD2)
N19596626: R85.2 U5.31(STATUS_LD1)
N19596640: C88.1 U5.12(LDObyp2)
N19596641: C87.1 U5.11(LDObyp1)
N19596650: D4.1(ANODE) R81.1
N19596653: R82.2 U5.59(CLKin_SEL1)
N19596656: R81.2 U5.58(CLKin_SEL0)
N19631315: C74.1 C76.1 C150.1 C151.1 FB16.1 U6.1(OUT1) U6.3(SENSE) U6.20(OUT2)
N19631466: C98.1 U6.14(NR)
N19631491: R83.2 U6.8(1P6V)
N19631493: R75.2 U6.11(0P2V)
N19631495: R72.2 U6.12(0P1V)
N19631505: R76.2 U6.10(0P4V)
N19740812: C183.1 U2.6(NR)
N19741196: R125.2 R126.1 U2.5(EN)
N19751506: C49.1 T5.5(GND)
N19764898: C137.2 R124.1 R176.2 U2.3(FB/SNS)
N19785823: C3.2 R63.2
N19785833: C3.1 R101.1
N19786108: C9.2 R107.2
N19786128: C9.1 R119.1
N19791732: C158.1 T4.4(primary_dot)
N19791735: C157.1 T4.6(primary_ct)
N19818342: C123.1 C127.1 C128.1 C129.1 C263.1 FB13.1 R50.1 U10.1(OUT1) U10.2(OUT2)
N19818462: C134.1 U10.6(NR)
N19818472: R161.2 R162.1 U10.5(EN)
N19818541: C129.2 R116.1 R174.2 U10.3(FB/SNS)
N19839460: R28.2 R29.1 U15.1(EN)
N19839464: C195.1 L2.2 R28.1 U15.7(VIN)
N19839484: L4.1 U15.6(SW)
N19839486: C196.1 R33.2 R37.1 U15.4(VOS)
N19839498: C197.1 C198.1 C271.1 L3.1 L4.2 R33.1
N19839502: C196.2 R32.1 R37.2 U15.3(FB)
N19884960: C201.1 R143.1 R144.2
N19885012: C274.1 T7.4(primary_dot)
N19885116: C276.2 R145.2
N19885138: C276.1 R146.1
N19885156: C277.2 T6.2(secondary) T6.5(primary)
N19885198: C200.2 T7.2(secondary) T7.5(primary)
N19885294: C203.1 T9.4(primary_dot)
N19885373: C206.1 R155.2 R156.1
N19885375: C204.2 T8.2(secondary) T8.5(primary)
N19885421: C205.2 T9.2(secondary) T9.5(primary)
N19885585: C207.2 R157.2
N19885597: C207.1 R158.1
N19895674: R182.2 R183.1 R186.1 U1.72(SYNCbCDP)
N19895681: R182.1 R184.2 R185.1 U1.71(SYNCbCDM)
N19922962: C141.1 T2.4(primary_dot)
N19926392: C4.2 T1.2(secondary) T1.5(primary)
N19927040: C5.2 T2.2(secondary) T2.5(primary)
N19928466: C202.1 T9.6(primary_ct)
N19936516: C140.1 T2.6(primary_ct)
N19989779: C275.1 T7.6(primary_ct)
N20022529: R50.2 R174.1
N20035911: R123.2 R176.1
N20038291: C265.1 U9.15(SS)
N20038313: R166.2 R167.1 U9.11(EN)
N20038327: R64.2 R175.1
N20038329: R128.1 R175.2 U9.16(FB/SNS)
N20038355: C115.1 C116.1 C117.1 R64.1 R129.1 U9.1(OUT4) U9.18(OUT1) U9.19(OUT2) U9.20(OUT3)
N20039194: C286.1 U16.6(NR)
N20039222: R177.2 R178.1 U16.5(EN)
N20039339: C283.1 C284.1 C285.1 C287.1 FB17.1 R180.1 U16.1(OUT1) U16.2(OUT2)
N20039347: C287.2 R180.2 R181.1 U16.3(FB/SNS)
N20052215: C290.1 T5.2(primary)
N20058798: C184.1 R187.2 U9.10(BIAS)
N20074843: C114.1 U11.6(NR)
N20074851: R188.2 R189.1 U11.5(EN)
N20074920: C106.2 R47.2 R48.1 U11.3(FB/SNS)
N20074982: R45.2 R47.1
N20087123: C66.2 R65.1
N20087124: C65.2 R66.1

Not connected (* = marked no-connect by the designer): J3 A14 A15 A18 A19 A22 A23 A26 A27 A30 A31 A34 A35 A38 A39 B1 B4 B5 B8 B9 B12 B13 B16 B17 B20 B21 B24 B25 B28 B29 B32 B33 B36 B37 B40 C2 C3 C10 C11 C19 C22 C23 C26 C27 C30 C31 C34 C35 C37 C39 D1 D8 D9 D11 D12 D17 D18 D20 D21 D23 D24 D26 D27 D29 D30 D31 D32 D33 D34 D35 D36 D38 D40 E2 E3 E6 E7 E9 E10 E12 E13 E15 E16 E18 E19 E21 E22 E24 E25 E27 E28 E30 E31 E33 E34 E36 E37 E39 F1 F4 F5 F7 F8 F10 F11 F13 F14 F16 F17 F19 F20 F22 F23 F25 F26 F28 F29 F31 F32 F34 F35 F37 F38 F40 G2 G3 G18 G19 G21 G22 G24 G25 G27 G28 G30 G31 G33 G34 G36 G37 G39 H1 H4 H5 H7 H8 H10 H11 H13 H14 H19 H20 H22 H23 H25 H26 H28 H29 H34 H35 H37 H38 H40 J2 J3 J6 J7 J9 J10 J12 J13 J15 J16 J18 J19 J21 J22 J24 J25 J27 J28 J30 J31 J33 J34 J36 J37 J39 K1 K4 K5 K7 K8 K10 K11 K13 K14 K16 K17 K19 K20 K22 K23 K25 K26 K31 K32 K34 K35 K40; J15 6* 7* 8*; T5 1(NC)*; U1 22(NC1)* 23(NC2)*; U3 12(IO_1_12/CLK0)* 14(IO_1_14/CLK1)* 16(IO_1_16/DIFFIO_L4P) 17(IO_1_17/DIFFIO_L4N) 18(IO_1_18/DIFFIO_L5P) 19(IO_1_19/DIFFIO_L5N) 20(IO_1_20/DIFFIO_L6P) 21(IO_1_21/DIFFIO_L6N) 26(IO_1_26/DIFFIO_B1P) 27(IO_1_27/DIFFIO_B1N) 28(IO_1_28/DIFFIO_B2P) 29(IO_1_29/DIFFIO_B2N) 30(IO_1_30/DIFFIO_B3P) 37(IO_1_37/DIFFIO_B5N) 38(IO_1) 39(IO_1_39/DIFFIO_B6P) 40(IO_1_40/DIFFIO_B6N) 41(IO_1_41/DIFFIO_B7P) 42(IO_1_42/DIFFIO_B7N) 43(IO_1_43/DEV_OE/DIFFIO_B8P)* 44(IO_1_44/DEV_CLRN/DIFFIO_B5N)* 47(IO_1_47/DIFFIO_B9P) 48(IO_1_48/DIFFIO_B9N) 49(IO_1) 50(IO_1_50/DIFFIO_B10P) 62(IO_2_62/CLK2)* 64(IO_2_64/CLK3)* 66(IO_2_66/DIFFIO_R4N) 67(IO_2_67/DIFFIO_R4P) 68(IO_2_68/DIFFIO_R3N) 69(IO_2_69/DIFFIO_R3P) 70(IO_2) 71(IO_2_71/DIFFIO_R2N) 72(IO_2_72/DIFFIO_R2P) 73(IO_2_73/DIFFIO_R1N) 74(IO_2_74/DIFFIO_R1P) 75(IO_2_75/DIFFIO_T10N) 82(IO_2_82/DIFFIO_T8P) 83(IO_2_83/DIFFIO_T7N) 84(IO_2_84/DIFFIO_T7P) 85(IO_2_85/DIFFIO_T6N) 86(IO_2_86/DIFFIO_T6P) 87(IO_2_87/DIFFIO_T5N) 88(IO_2_88/DIFFIO_T5P) 89(IO_2_89/DIFFIO_T4N) 90(IO_2_90/DIFFIO_T4P) 91(IO_2) 92(IO_2_92/DIFFIO_T3N) 95(IO_2_95/DIFFIO_T3P) 96(IO_2_96/DIFFIO_T2N) 97(IO_2_97/DIFFIO_T2P) 98(IO_2_98/DIFFIO_T1N) 99(IO_2_99/DIFFIO_T1P) 100(IO_2); U5 22(SDCLKOUT5p)* 23(SDCLKOUT5n)* 24(DCLKOUT4p)* 25(DCLKOUT4n)* 27(DCLKOUT6p) 28(DCLKOUT6n) 29(SDCLKOUT7p) 30(SDCLKOUT7n) 37(CLKIN0p)* 38(CLKIN0n)* 40(OSCOUTp)* 41(OSCOUTn)* 49(SDCLKOUT9p)* 50(SDCLKOUT9n)* 51(DCLKOUT8p)* 52(DCLKOUT8n)* 54(DCLKOUT10p)* 55(DCLKOUT10n)* 56(SDCLKOUT11p)* 57(SDCLKOUT11n)* 60(SDCLKOUT13p)* 61(SDCLKOUT13n)*; U6 2(NC1)* 4(6P4V2)* 5(6P4V1)* 6(3P2V)* 9(0P8V)* 17(NC2)* 18(NC3)* 19(NC4)*; U7 8(NC1)* 12(PWREN)* 13(RD)* 14(WR)* 19(RESET)* 22(TXE)* 23(RXF)* 24(NC2)* 27(OSCI)* 28(OSCO)*; U9 9(PG)*; U12 1(NC1)* 3(NC3)*; U15 2(PG)*

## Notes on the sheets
sheet 1
- FMC_CLK* & FMC_SYSREF* DIFF PAIRS
- MUST BE MATCHED LENGTH
- TO EACH OTHER.
sheet 2
- FMC
- USB
- CPLD
sheet 3
- FPGA* DIFF PAIRS MUST BE
- MATCHED LENGTH TO EACH OTHER.
- C122 & R100 PLACE CLOSE TO LMK
- PLACE C120 CLOSE TO Y1
- CLK* & SYSREF* DIFF PAIRS MUST BE
- MATCHED LENGTH TO EACH OTHER.
- C92 & C121 SHARED PAD
- C92, C121 & R102 PLACE CLOSE TO LMK
- C82 & R77 PLACE CLOSE TO LMK
- CLK_LA0* DIFF PAIRS MUST BE
- MATCHED LENGTH TO THE FPGA PAIRS.
- 12500 TI Boulevard. Dallas, Texas 75243
sheet 4
- MAIN PWR
- ADS* PWR
- USB
- ADC/LMK GUI
- PAGES 9 & 10
- PAGE 7
- SPI
- JESD204B DATA
- SMA
- XTF
- FMC
- CONNECTOR
- PAGE 2
- PAGE 2
- SYNCB
- SPI
- PAGE 6
- ADS58J64
- CPLD
- SMA
- SPI
- XTF
- PAGE 8
- PAGE 2
- PAGE 3
- PAGE 2
- SMA
- XTF
- CLK
- SYSREF
- PAGE 2
- PAGE 2
- SPI
- CLK
- SYSREF
- SMA
- XTF
- PAGE 2
- PAGE 2
- LMK04828
- PAGE 4
- 12500 TI Boulevard. Dallas, Texas 75243
- LMK* PWR
- PAGE 5
- Engineer:
- J CARNES  02/2016
- PCB:
- L NGUYEN 02/2016
sheet 5
- 12500 TI Boulevard. Dallas, Texas 75243
sheet 6
- DNI = DO NOT INSTALL
- R34 & R133 place next to U1
- Place resistor on trace.
- No stub.
- R30 SHARES A PAD WITH C190
- R31 SHARES A PAD WITH C191
- FMC_CLK* & FMC_SYSREF* DIFF PAIRS
- MUST BE MATCHED LENGTH
- TO EACH OTHER.
- R35, C47 AND C192 SHARE A PAD.
- R39, C48 AND C193 SHARE A PAD.
- 30MHz to 3GHz
- 12500 TI Boulevard. Dallas, Texas 75243
sheet 7
- PLACE FB*S NEXT TO U5
sheet 9
- 3A
sheet 10
- +1.4V, 1A
- MECHANICAL PARTS
